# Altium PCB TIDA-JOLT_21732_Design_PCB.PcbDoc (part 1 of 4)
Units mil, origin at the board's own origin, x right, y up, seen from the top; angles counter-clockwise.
Board outline 5511.81 x 3149.61 mil, 4 copper layers (Top Layer, Power, Ground, Bottom Layer), stack 104.204 mil thick; 440 components, 201 nets, 1044 pads, 391 vias.
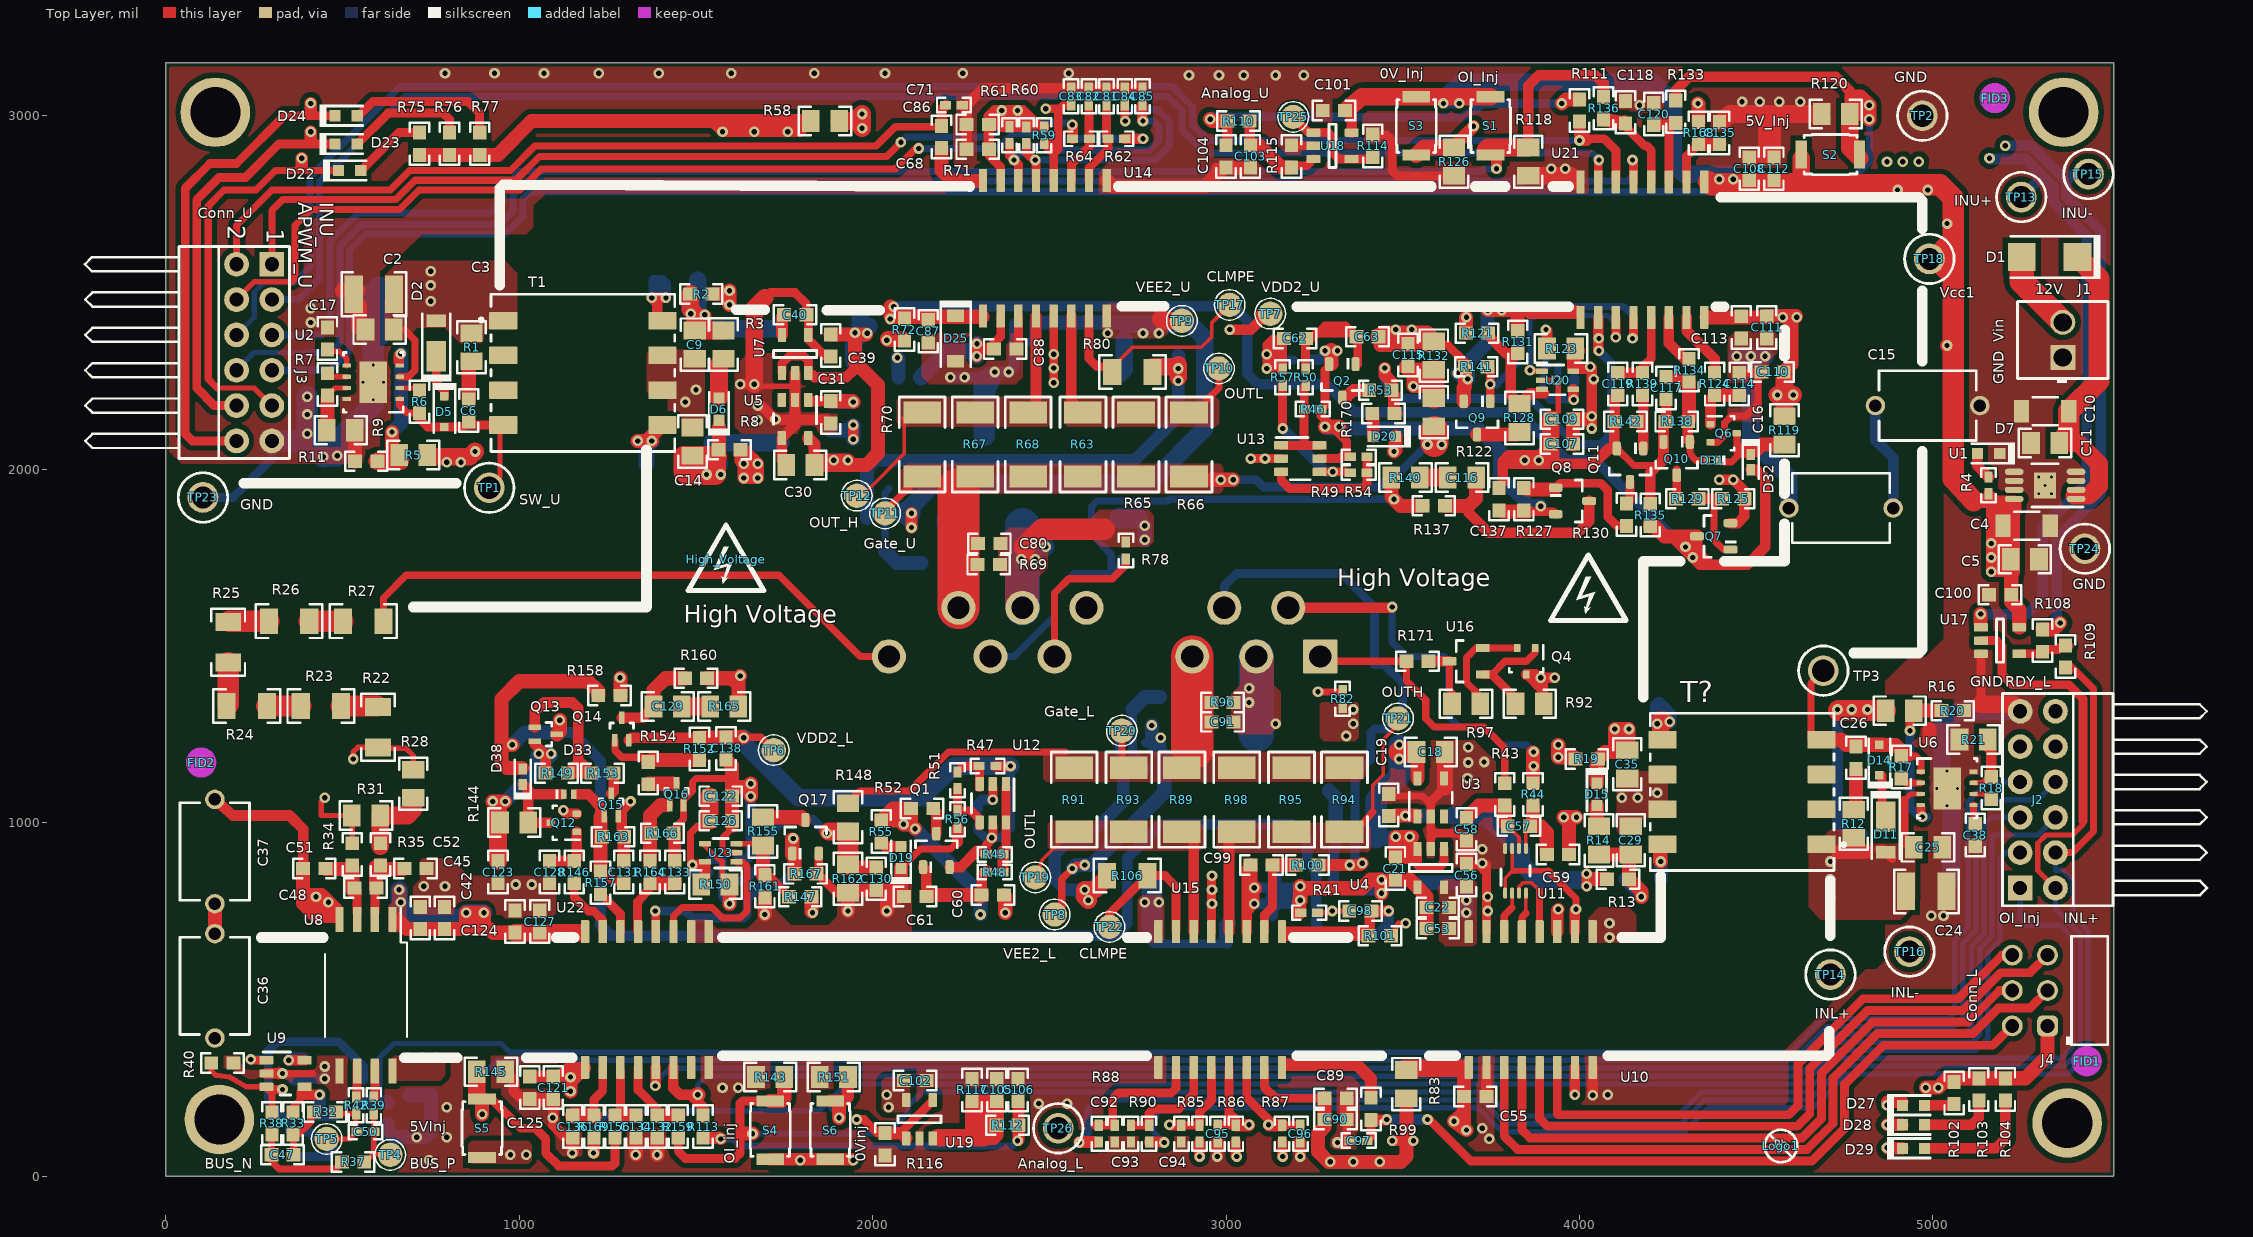
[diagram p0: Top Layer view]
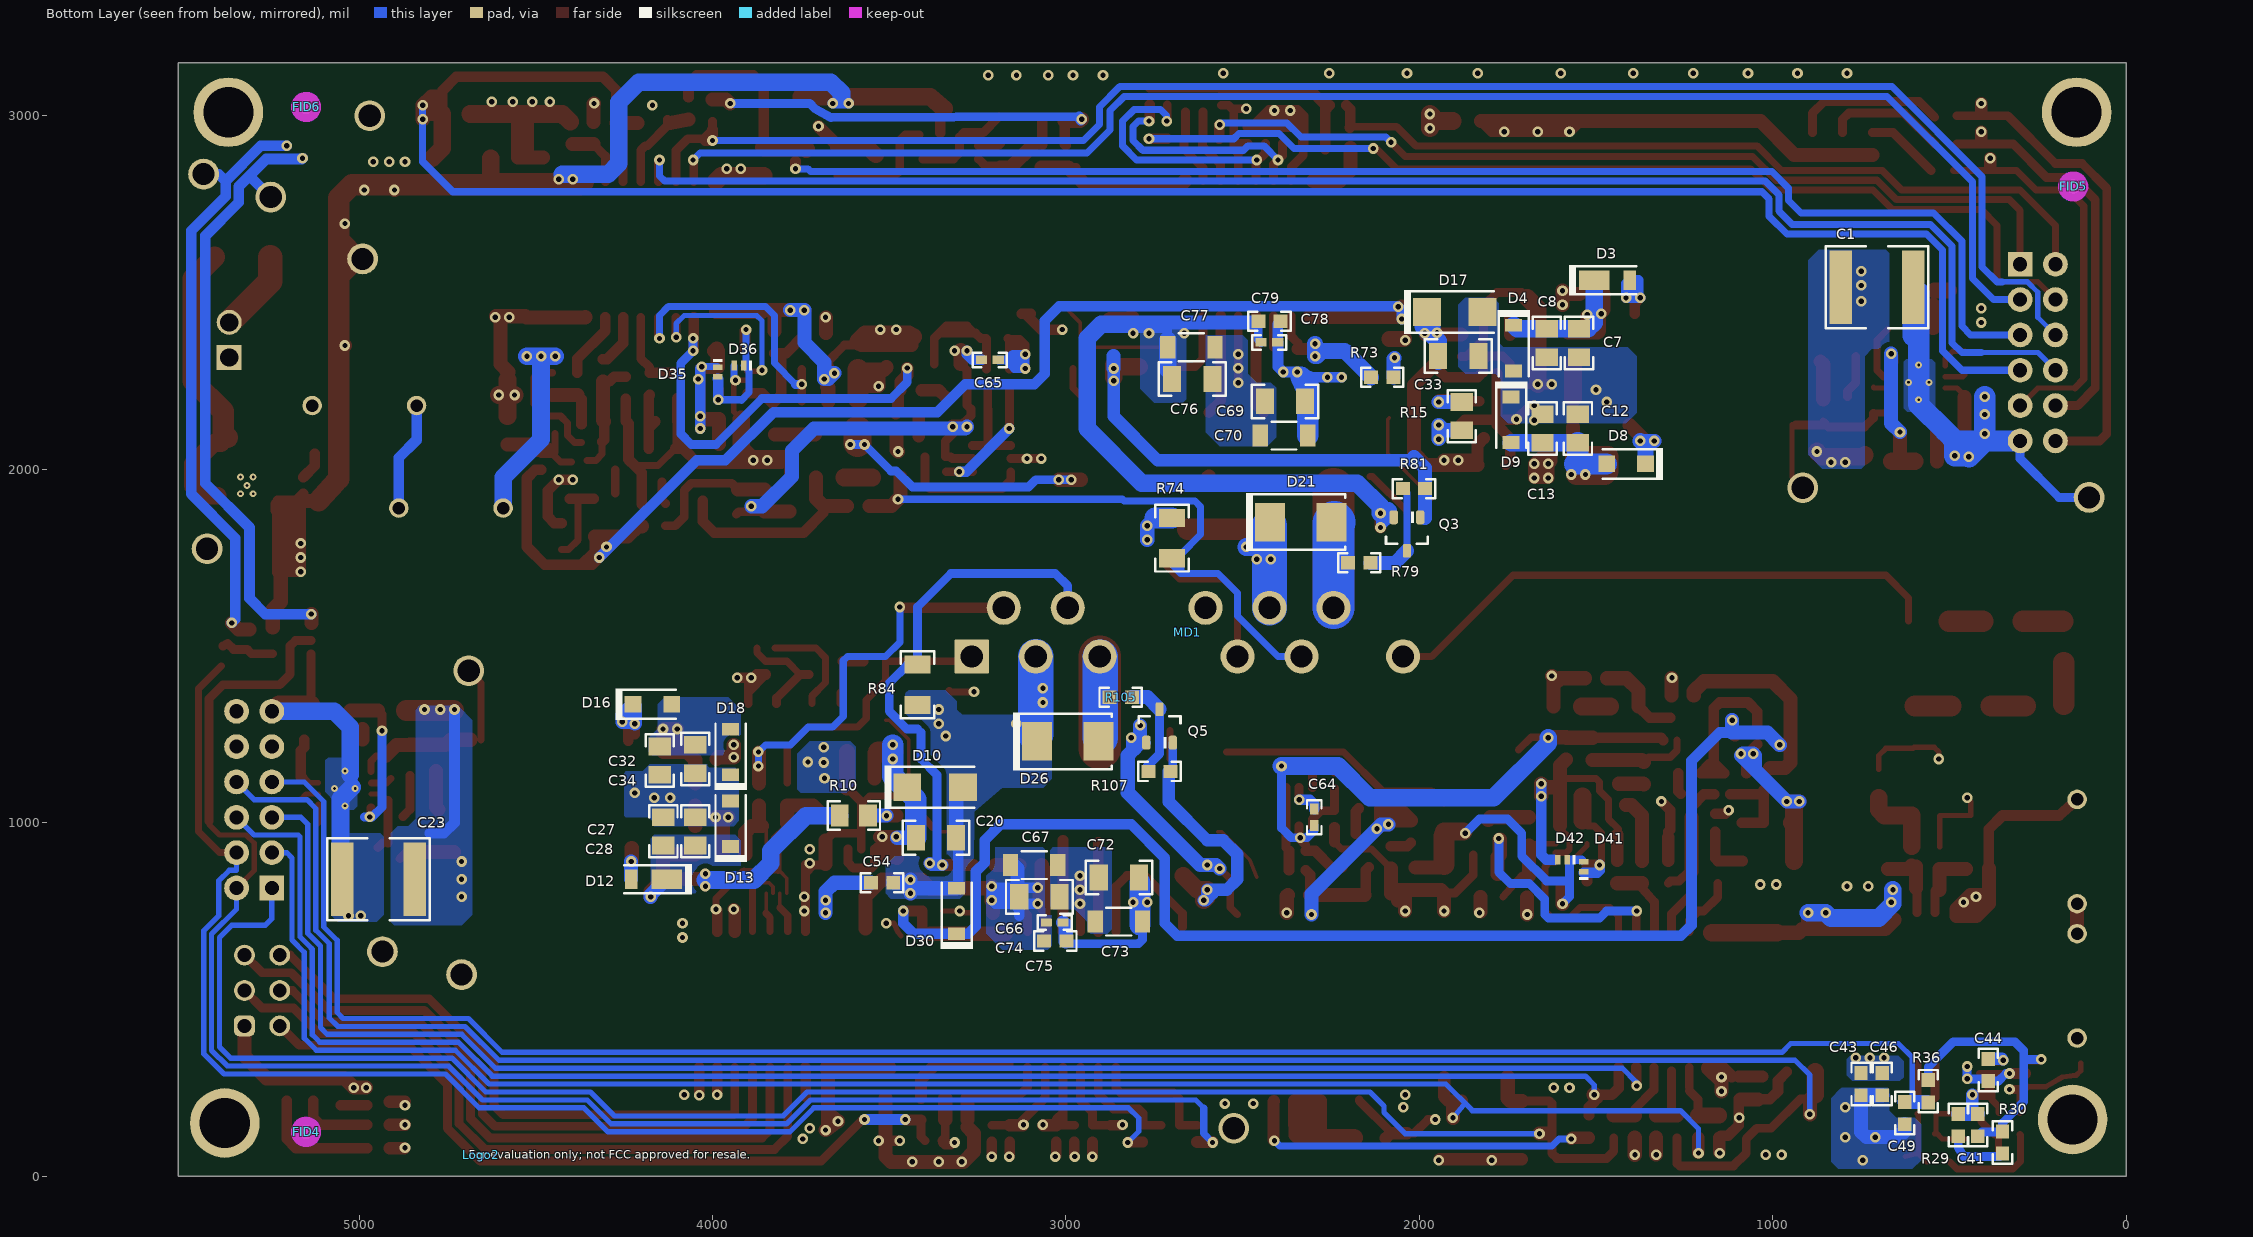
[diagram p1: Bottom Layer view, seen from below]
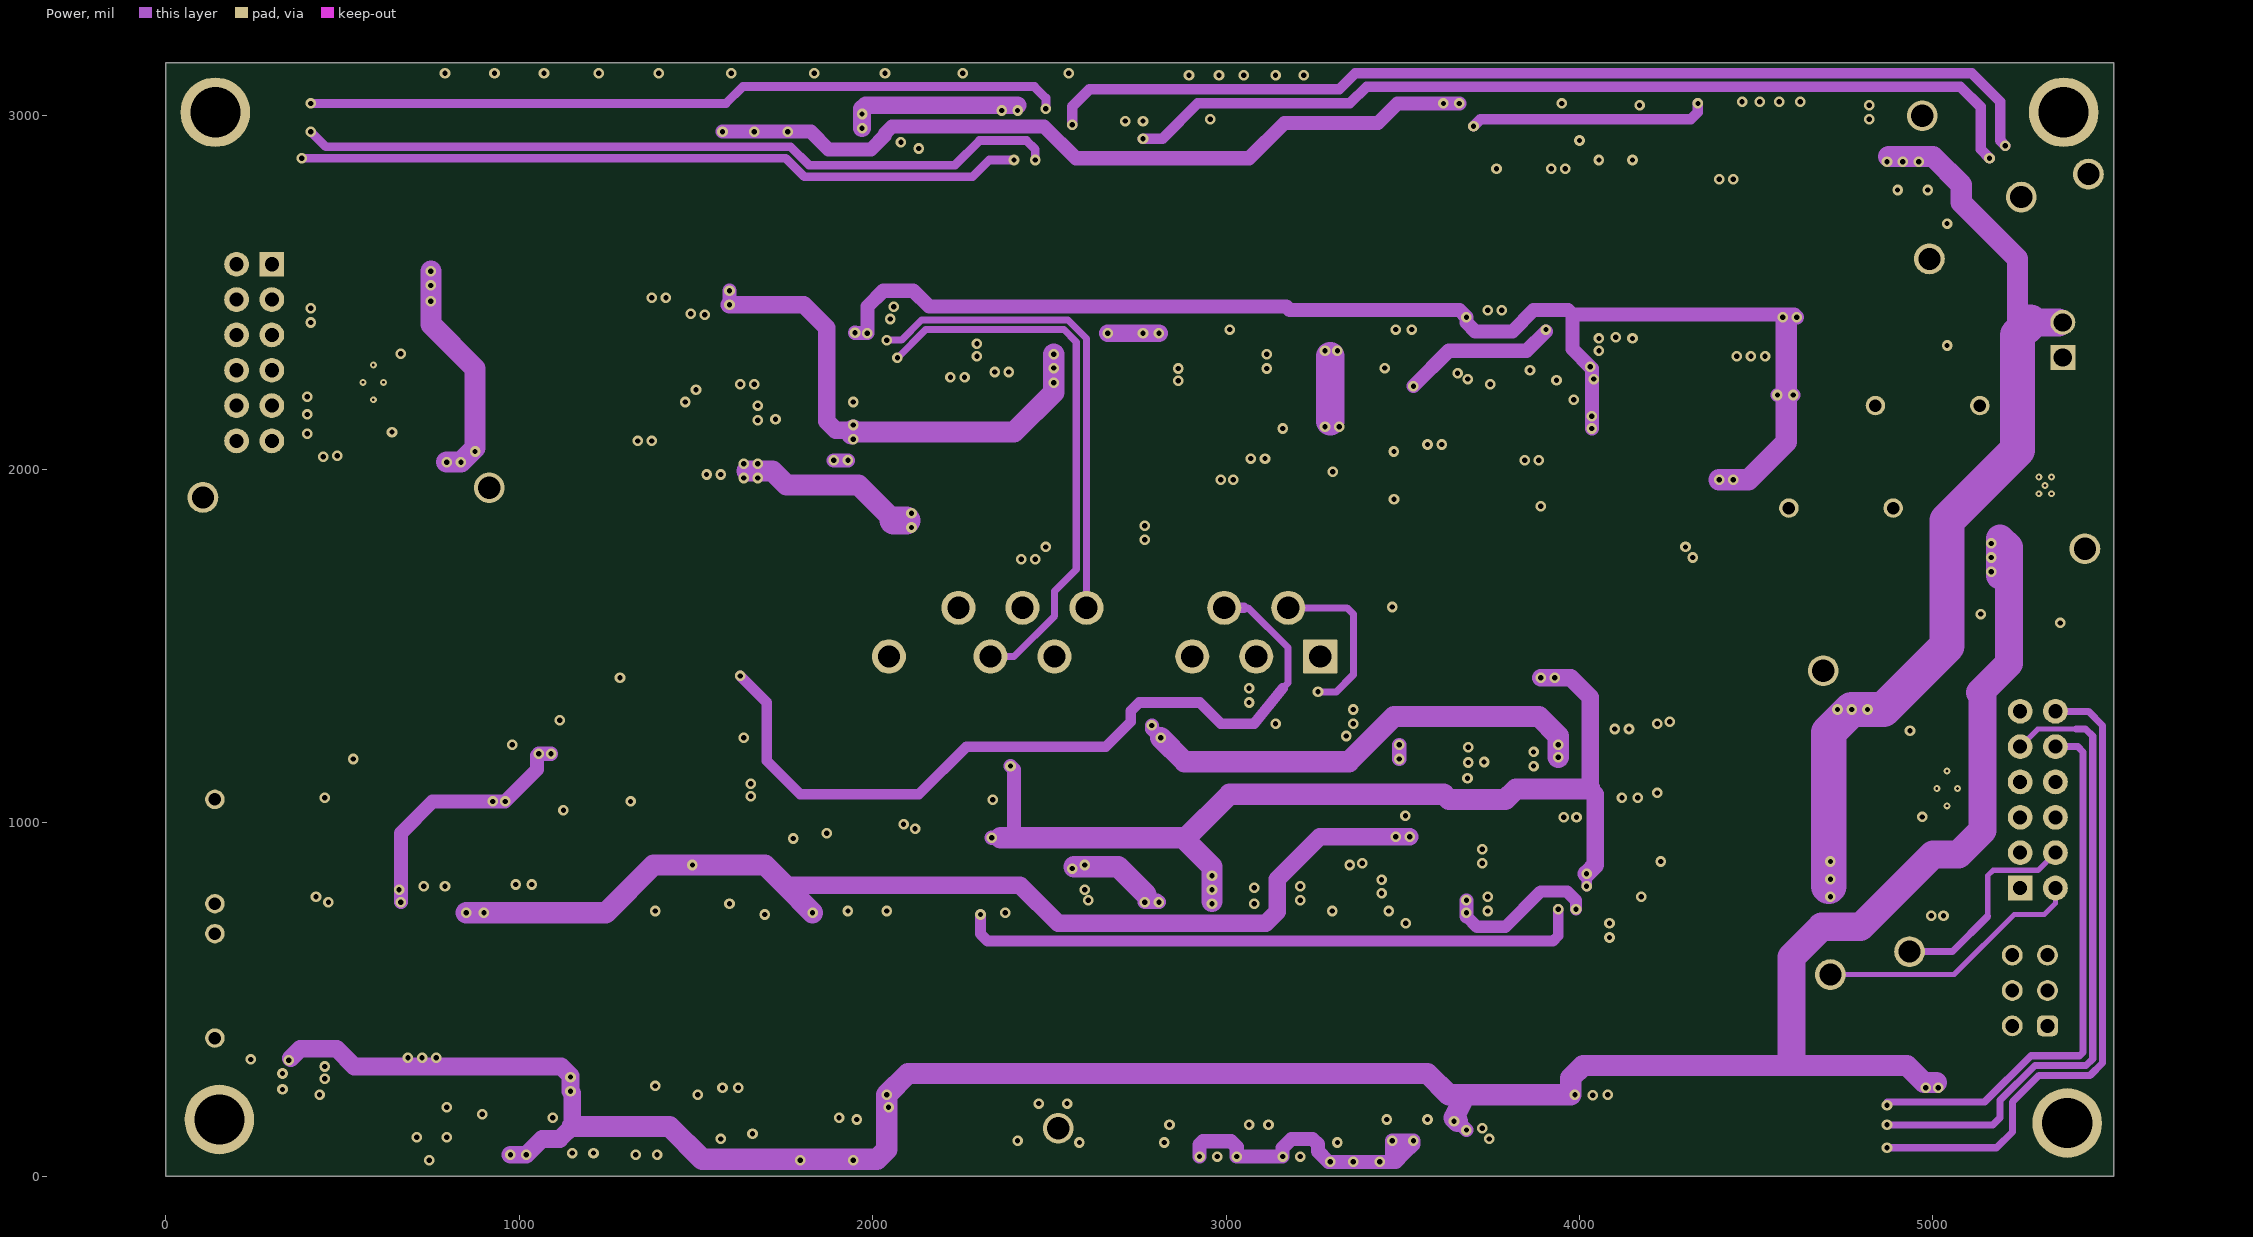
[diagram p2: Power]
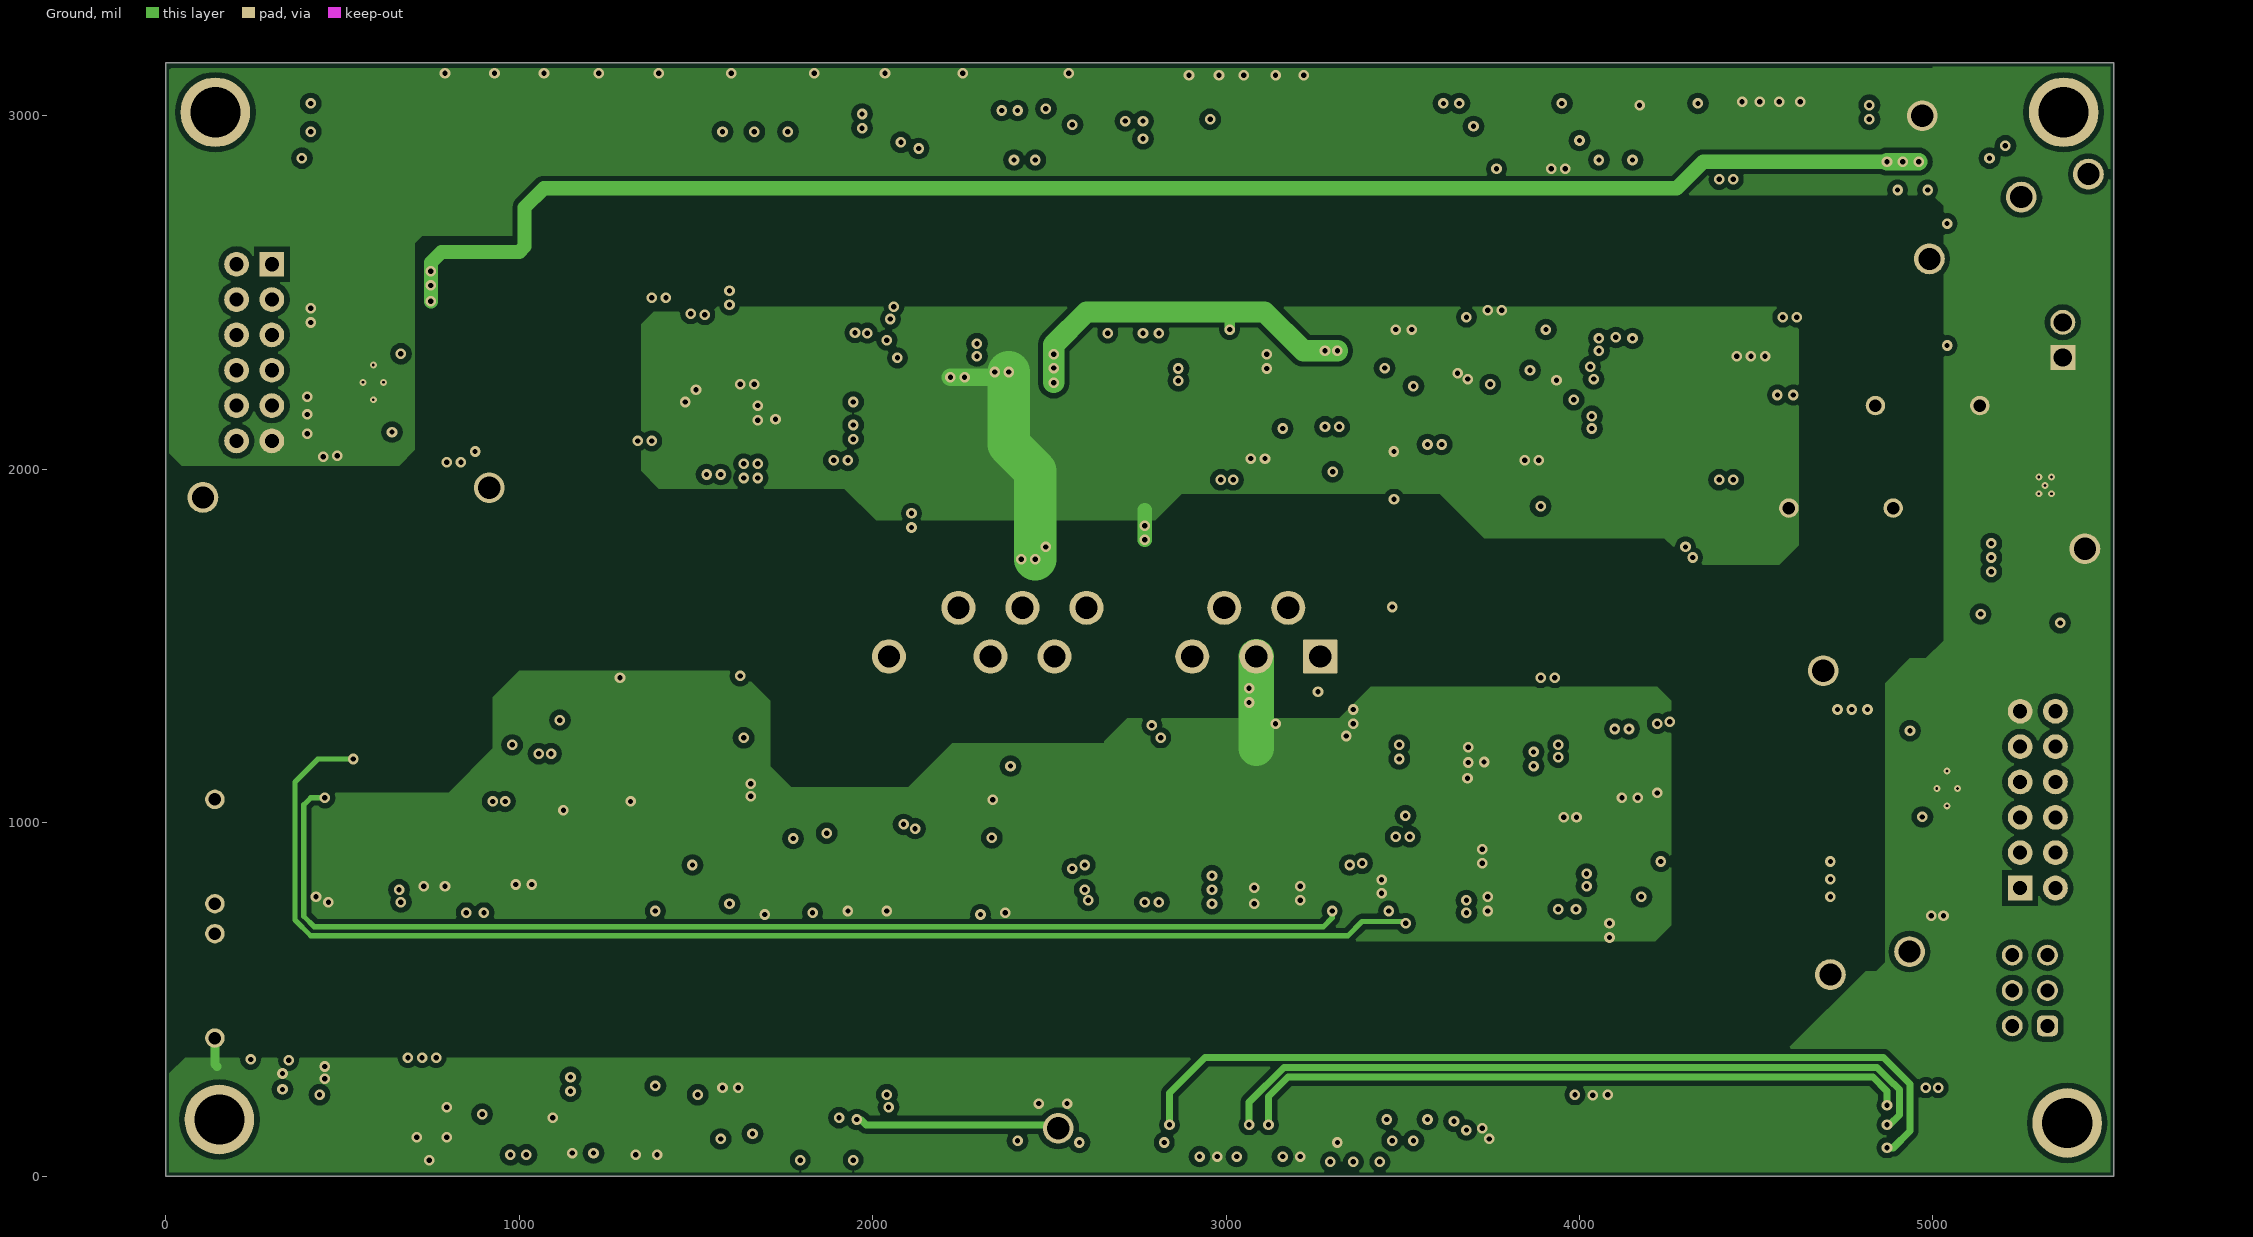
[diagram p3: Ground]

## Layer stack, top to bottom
Top Solder: solder mask 0.4, Solder Resist, Dk 3.5
Top Layer: signal copper 1.4
Dielectric 2: prepreg 19.685, FR-4, Dk 4.2
Power: signal copper 1.417
Dielectric1: core 59.2, FR-4, Dk 4.8
Ground: signal copper 1.417
Dielectric 3: prepreg 19.685, FR-4, Dk 4.2
Bottom Layer: signal copper 1.4
Bottom Solder: solder mask 0.4, Solder Resist, Dk 3.5

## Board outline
0,0 0,3149.61 5511.81,3149.61 5511.81,0

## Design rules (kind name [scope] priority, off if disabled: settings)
AcuteAngle [All] p1: minimum=4.50000000000000E+0001 checktracksonly=FALSE
AssemblyTestPointUsage [All] p1: valid=2
BoardOutlineClearance BoardOutlineClearance_MountingHoles [OnCopper and InComponentClass('Mounting Holes')] p1: gap=40 ignorepadtopadclearanceinfootprint=FALSE
BoardOutlineClearance BoardOutlineClearance_Poly [OnCopper and IsPoly] p2: gap=10 ignorepadtopadclearanceinfootprint=FALSE
BoardOutlineClearance [OnCopper and Not InComponentClass('Logo') and not InComponentClass('FiducialMark') and not InRegion(1000,500,4000,800) and not InPoly] p3: gap=10 ignorepadtopadclearanceinfootprint=FALSE
Clearance Clearance_Keepouts [((IsTrack Or IsArc) And Not InPoly) And IsFree and IsKeepOut vs ((IsTrack Or IsArc) And Not InPoly) And IsFree and IsKeepOut] p1: gap=0 ignorepadtopadclearanceinfootprint=FALSE
Clearance Clearance_Poly [InPolygon] p2: gap=15 ignorepadtopadclearanceinfootprint=FALSE
Clearance Clearance_FiducialMark [IsKeepOut and InComponentClass('FiducialMark') vs IsPad and InComponentClass('FiducialMark')] p3: gap=0 ignorepadtopadclearanceinfootprint=FALSE
Clearance [All] p4: gap=7.45 ignorepadtopadclearanceinfootprint=FALSE
ComponentClearance ComponentClearance_MountingHoles_FiducialMarks [InComponentClass('Mounting Holes') vs InComponentClass('FiducialMark')] p1: gap=50 collisioncheckmode=3 verticalgap=10 showdistances=FALSE
ComponentClearance ComponentClearance_Shunt [InComponentClass('Header') vs InComponentClass('Shunt')] p2: gap=0 collisioncheckmode=3 verticalgap=0 showdistances=FALSE
ComponentClearance ComponentClearance_Logo [InComponentClass('Logo')] p3: gap=50 collisioncheckmode=3 verticalgap=10 showdistances=FALSE
ComponentClearance ComponentClearance_ScrewToNut [(HasFootprint('NY PMS 440 0025 PH')) vs (HasFootprint('Keystone_1902C'))] p4: gap=5 collisioncheckmode=3 verticalgap=10 showdistances=FALSE
ComponentClearance ComponentClearance_MountingHoles [InComponentClass('Mounting Holes')] p5: gap=250 collisioncheckmode=3 verticalgap=100000 showdistances=FALSE
ComponentClearance ComponentClearance_SmallPassives [HasFootprint('0201*') or HasFootprint('0402*') or HasFootprint('0508') or HasFootprint('0603*') or HasFootprint('0612') or HasFootprint('0805*') or HasFootprint('0815*') or HasFootprint('0830*') or HasFootprint('1206*') or HasFootprint('1210*') or HasFootprint('1808*') or HasFootprint('1812*') or HasFootprint('1825*') or HasFootprint('2010*') or HasFootprint('2220*') or HasFootprint('2225*') or HasFootprint('2512*') or HasFootprint('2728*') or HasFootprint('3518*') vs HasFootprint('0201*') or HasFootprint('0402*') or HasFootprint('0508') or HasFootprint('0603*') or HasFootprint('0612') or HasFootprint('0805*') or HasFootprint('0815*') or HasFootprint('0830*') or HasFootprint('1206*') or HasFootprint('1210*') or HasFootprint('1808*') or HasFootprint('1812*') or HasFootprint('1825*') or HasFootprint('2010*') or HasFootprint('2220*') or HasFootprint('2225*') or HasFootprint('2512*') or HasFootprint('2728*') or HasFootprint('3518*')] p6: gap=14.96 collisioncheckmode=3 verticalgap=10 showdistances=FALSE
ComponentClearance ComponentClearance_THtoSMT [IsThruComponent vs IsSMTComponent] p7: gap=30 collisioncheckmode=3 verticalgap=30 showdistances=FALSE
ComponentClearance ComponentClearance_THtoTH [IsThruComponent vs IsThruComponent] p8: gap=30 collisioncheckmode=3 verticalgap=30 showdistances=FALSE
ComponentClearance [All] p9: gap=15 collisioncheckmode=3 verticalgap=10 showdistances=FALSE
DiffPairsRouting [All] p1: maxlimit=100 minlimit=10 mostfreqgap=10 toplayer_minwidth=15 toplayer_maxwidth=15 toplayer_prefwidth=15 midlayer1_minwidth=15 midlayer1_maxwidth=15 midlayer1_prefwidth=15 midlayer2_minwidth=15 midlayer2_maxwidth=15 midlayer2_prefwidth=15 bottomlayer_minwidth=15 bottomlayer_maxwidth=15 bottomlayer_prefwidth=15 maxuncoupledlength=1000
FabricationTestPointUsage TestPointUsage [All] p1: valid=2 allowmultiple=FALSE
FabricationTestpoint Testpoint [All] p1: side=3 testpointundercomponent=TRUE minsize=40 maxsize=100 preferedsize=60 minholesize=0 maxholesize=40 preferedholesize=32 testpointgrid=1 allowsidetop=TRUE allowsidebottom=TRUE usegrid=TRUE gridtolerance=0.01
FanoutControl Fanout_LCC [IsLCC] p1: bgadir=Out bgaviamode=Centered fanoutstyle=Auto fanoutdirection=Alternating viagrid=1 // Fanout_LCC (Default Rule)
FanoutControl Fanout_BGA [IsBGA] p2: bgadir=Out bgaviamode=Centered fanoutstyle=Auto fanoutdirection=Alternating viagrid=1 // Fanout_BGA (Default Rule)
FanoutControl Fanout_Default [All] p4: bgadir=Out bgaviamode=Centered fanoutstyle=Auto fanoutdirection=Alternating viagrid=1 // Fanout_Default (Default Rule)
FanoutControl Fanout_Small [(CompPinCount < 5)] p5: bgadir=Out bgaviamode=Centered fanoutstyle=Auto fanoutdirection=OutThenIn viagrid=1 // Fanout_Small (Default Rule)
Height [All] p1: minheight=0 maxheight=2500 prefheight=500
HoleSize [All] p1: absolutevalues=TRUE maxlimit=251 minlimit=7.87 maxpercent=80.000 minpercent=20.000
MinimumAnnularRing MinimumAnnularRing_ThermalPadVias [IsVia and InAnyComponent] p1: minimumring=5.91
MinimumAnnularRing [All] p2: minimumring=7
MinimumSolderMaskSliver MinimumSolderMaskSliver_Logo [InComponentClass('Logo') vs InComponentClass('Logo')] p1: minsoldermaskwidth=0.7
MinimumSolderMaskSliver [All] p2: minsoldermaskwidth=0
PlaneConnect [All] p1: planeconnectstyle=Direct reliefexpansion=10 reliefentries=4 reliefconductorwidth=10 reliefairgap=10
PolygonConnect [All] p1: connectstyle=Direct reliefconductorwidth=10 reliefentries=4 polygonreliefangle="90 Angle" airgapwidth=10
RoutingVias ThermalPadVias [IsVia and InAnyComponent] p1: holewidth=7.87 width=19.68 viastyle="Through Hole" minholewidth=7.87 minwidth=19.68 maxholewidth=12.99 maxwidth=23.62
RoutingVias [All] p2: holewidth=16 width=34 viastyle="Through Hole" minholewidth=7.87 minwidth=26 maxholewidth=40 maxwidth=65
SilkToBoardRegionClearance [Not ((IsComment or IsDesignator) And (Hide <> 'False')) and not InRegion(1000,500,4000,800)] p1:
SilkToSilkClearance SilkToSilkClearance_Pb-FreeLogo [(HasFootprint('Pb-Free_Overlay_Medium') OR HasFootprint('Pb-Free_Overlay_Small')) vs (HasFootprint('Pb-Free_Overlay_Medium') OR HasFootprint('Pb-Free_Overlay_Small'))] p1: silktosilkclearance=0
SilkToSilkClearance [All] p2: silktosilkclearance=4
SilkToSolderMaskClearance SilkToComponentPadClearance [(IsPad or IsFill or IsRegion) and InAnycomponent] p1: minsilkscreentomaskgap=0 clearancetoexposedcopper=TRUE
SilkToSolderMaskClearance "Silk to Solder Mask Opening" [All] p2: minsilkscreentomaskgap=0 clearancetoexposedcopper=FALSE
SolderMaskExpansion [All] p1: expansion=1.97
Width "Schematic Width Constraint" [InNetClass('PowerNets')] p1: maxlimit=120 minlimit=20 preferedwidth=80 midlayer1_minwidth=40 midlayer2_minwidth=40 minimp=50.000000 maximp=50.000000 favimp=50.000000
Width [All] p2: maxlimit=200 minlimit=6 preferedwidth=10 checkconnectedcopper=TRUE
14 further rules are at their usual default settings.

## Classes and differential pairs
component class AssemblyNote: ZZ1 ZZ2 ZZ3 ZZ4
component class FiducialMark: FID1 FID2 FID3 FID4 FID5 FID6
component class JOLT_21732_Design_EVM_Hardware: FID1 FID2 FID3 FID4 FID5 FID6 "High Voltage" High_Voltage Logo1 Logo2 ZZ1 ZZ2 ZZ3 ZZ4
component class Header: J2 J3 J4
component class JOLT_21732_Driver_Conn: C66 C67 C68 C69 C70 C71 C72 C73 C74 C75 C76 C77 C78 C79 C80 C81 C82 C83 C84 C85 C86 C87 C88 C89 C90 C91 C92 C93 C94 C95 C96 C97 C98 C99 C100 D21 D22 D23 D24 D25 D26 D27 D28 D29 D30 J2 J3 J4 MD1 Q3 Q4 Q5 R58 R59 R60 R61 R62 R63 R64 R65 R66 R67 R68 R69 R70 R71 R72 R73 R74 R75 R76 R77 R78 R79 R80 R81 R82 R83 R84 R85 R86 R87 R88 R89 R90 R91 R92 R93 R94 R95 R96 R97 R98 R99 R100 R101 R102 R103 R104 R105 R106 R107 R108 R109 R171 TP6 TP7 TP8 TP9 TP10 TP11 TP12 TP13 TP14 TP15 TP16 TP17 TP18 TP19 TP20 TP21 TP22 TP23 TP24 U14 U15 U16 U17
component class JOLT_21732_OI_AIN_PWM_check: C101 C102 C103 C104 C105 C106 C107 C108 C109 C110 C111 C112 C113 C114 C115 C116 C117 C118 C119 C120 C121 C122 C123 C124 C125 C126 C127 C128 C129 C130 C131 C132 C133 C134 C135 C136 C137 C138 D31 D32 D33 D35 D36 D38 D41 D42 Q6 Q7 Q8 Q9 Q10 Q11 Q12 Q13 Q14 Q15 Q16 Q17 R110 R111 R112 R113 R114 R115 R116 R117 R118 R119 R120 R121 R122 R123 R124 R125 R126 R127 R128 R129 R130 R131 R132 R133 R134 R135 R136 R137 R138 R139 R140 R141 R142 R143 R144 R145 R146 R147 R148 R149 R150 R151 R152 R153 R154 R155 R156 R157 R158 R159 R160 R161 R162 R163 R164 R165 R166 R167 R168 R169 S1 S2 S3 S4 S5 S6 TP25 TP26 U18 U19 U20 U21 U22 U23
component class JOLT_21732_Supply_Bias: C1 C2 C3 C4 C5 C6 C7 C8 C9 C10 C11 C12 C13 C14 C15 C16 C17 C18 C19 C20 C21 C22 C23 C24 C25 C26 C27 C28 C29 C30 C31 C32 C33 C34 C35 C36 C37 C38 C39 C40 D1 D2 D3 D4 D5 D6 D7 D8 D9 D10 D11 D12 D13 D14 D15 D16 D17 D18 J1 R1 R2 R3 R4 R5 R6 R7 R8 R9 R10 R11 R12 R13 R14 R15 R16 R17 R18 R19 R20 R21 T1 T? TP1 TP2 TP3 U1 U2 U3 U4 U5 U6 U7
net class PowerNets: +5V_L +5V_U VCC1
differential pair BUSIN: +BUSIN_P -BUSIN_N
differential pair BUS: +BUS_P -BUS_N

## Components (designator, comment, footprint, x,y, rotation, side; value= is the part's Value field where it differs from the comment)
C1 "C5750X7S2A106K230KB" 2220_250 705,2515 r180 bottom value=10uF
C2 "GCM32DC72A475KE02L" 1210_220 588.86,2495 r180 top value=4.7uF
C3 "GRM21BR72A104KAC4L" 0805_HV 605,2395 r180 top value=0.1uF
C4 "GRM31CR71E106KA12L" 1206_180 5265,1840 r0 top value=10uF
C5 "GRM21BR71H104KA01L" 0805_HV 5260,1745 r0 top value=0.1uF
C6 "GRM1885C2A221JA01D" 0603 857.1,2165.76 r270 top value=220pF
C7 "GRM21BR61E226ME44L" 0805_HV 1548.2,2357.02 r270 bottom value=22uF
C8 "GRM21BR61E226ME44L" 0805_HV 1639.22,2357.02 r270 bottom value=22uF
C9 "GRM21BR71H224KA01L" 0805_HV 1496.85,2352.39 r270 top value=0.22uF
C10 "GRM31CR71H225KA88L" 1206_180 5317.4,2164.13 r180 top value=2.2uF
C11 "GRM21BR71H104KA01L" 0805_HV 5317.4,2074.13 r180 top value=0.1uF
C12 "GRM21BR61E226ME44L" 0805_HV 1551.46,2115 r270 bottom value=22uF
C13 "GRM21BR61E226ME44L" 0805_HV 1651.46,2115 r270 bottom value=22uF
C14 "GRM21BR71H224KA01L" 0805_HV 1490,2078.03 r270 top value=0.22uF
C15 "DE2E3KY152MN3AM02F" KY_700x500x1000 4985,2180 r0 top value=1500pF
C16 "DE2E3KY152MN3AM02F" KY_700x500x1000 4740,1890 r0 top value=1500pF
C17 "GRM188R71C473KA01D" 0603 457.1,2370 r90 top value=0.047uF
C18 "C2012X5R1E106K125AB" 0805_HV 3578.98,1200 r180 top value=10uF
C19 "UMK107AB7105KA-T" 0603 3460,1050 r90 top value=1uF
C20 "C1206C225K4RACTU" 1206 3367.56,957.27 r180 bottom value=2.2uF
C21 "GRM188R71E105KA12D" 0603 3478.98,870 r270 top value=1uF
C22 "GRM188R71E105KA12D" 0603 3598.98,760 r180 top value=1uF
C23 "C5750X7S2A106K230KB" 2220_250 4945,840 r0 bottom value=10uF
C24 "GCM32DC72A475KE02L" 1210_220 4981.3,805.47 r0 top value=4.7uF
C25 "GRM21BR72A104KAC4L" 0805_HV 4986.1,930 r0 top value=0.1uF
C26 "GRM1885C2A221JA01D" 0603 4782.41,1183.46 r90 top value=220pF
C27 "GRM21BR61E226ME44L" 0805_HV 4138.98,975.35 r90 bottom value=22uF
C28 "GRM21BR61E226ME44L" 0805_HV 4048.98,975.35 r90 bottom value=22uF
C29 "GRM21BR71H224KA01L" 0805_HV 4145,950 r90 top value=0.22uF
C30 "C2012X5R1E106K125AB" 0805_HV 1795.28,2012.14 r0 top value=10uF
C31 "UMK107AB7105KA-T" 0603 1881.3,2160.88 r270 top value=1uF
C32 "GRM21BR61E226ME44L" 0805_HV 4148.98,1175.35 r90 bottom value=22uF
C33 "C1206C225K4RACTU" 1206 1889.75,2320.57 r180 bottom value=2.2uF
C34 "GRM21BR61E226ME44L" 0805_HV 4048.98,1180 r90 bottom value=22uF
C35 "GRM21BR71H224KA01L" 0805_HV 4135,1165 r90 top value=0.22uF
C36 "DE2E3KY152MN3AM02F" KY_700x500x1000 138.7,538.11 r270 top value=1500pF
C37 "DE2E3KY152MN3AM02F" KY_700x500x1000 138.7,918.11 r270 top value=1500pF
C38 "GRM188R71C473KA01D" 0603 5120,964.87 r270 top value=0.047uF
C39 "GRM188R71E105KA12D" 0603 1881.3,2350 r270 top value=1uF
C40 "GRM188R71E105KA12D" 0603 1780.7,2437.14 r0 top value=1uF
C41 "GRM188R71H103KA01D" 0603 420,144.13 r270 bottom value=0.01uF
C42 "GRM188R71H104KA93D" 0603 788.74,730 r90 top value=0.1uF
C43 "GRM188R71H104KA93D" 0603 750,260 r270 bottom value=0.1uF
C44 "GRM188R71E105KA12D" 0603 390,300 r90 bottom value=1uF
C45 "GRM188R71E105KA12D" 0603 720.04,730 r270 top value=1uF
C46 "GRM188R71E105KA12D" 0603 690,260 r90 bottom value=1uF
C47 "GRM188R71H103KA01D" 0603 330,60 r180 top value=0.01uF
C48 "GRM188R71H103KA01D" 0603 565,815 r0 top value=0.01uF
C49 "GRM188R71H104KA93D" 0603 626.69,178.03 r270 bottom value=0.1uF
C50 "Capacitor" 0402 565,125 r180 top value=0.1uF
C51 "GRM188R71H102KA01D" 0603 420,870 r180 top value=1000pF
C52 "GRM188R71H102KA01D" 0603 706.38,870 r0 top value=1000pF
C53 "GRM188R71E105KA12D" 0603 3598.98,700 r0 top value=1uF
C54 "GRM188R71E105KA12D" 0603 3520,830 r180 bottom value=1uF
C55 "GRM188R71E105KA12D" 0603 3705,225 r180 top value=1uF
C56 "GRM188R71H104KA93D" 0603 3680.28,851.26 r270 top value=0.1uF
C57 "GRM188R71H103KA01D" 0603 3828.5,990 r180 top value=0.01uF
C58 "GRM188R71H102KA01D" 0603 3680.28,981.26 r90 top value=1000pF
C59 "GRM188R71H102KA01D" 0603 3938.98,910 r180 top value=1000pF
C60 "GRM1885C2A101JA01D" 0603 2340,795 r0 top value=100pF
C61 "GRM1885C2A101JA01D" 0603 2120.24,791.26 r180 top value=100pF
C62 "GRM1885C2A101JA01D" 0603 3195,2370 r180 top value=100pF
C63 "GRM1885C2A101JA01D" 0603 3400,2375 r0 top value=100pF
C64 "Capacitor" 0402 2297.32,1015 r90 bottom value=0.1uF
C65 "Capacitor" 0402 3215,2309.21 r180 bottom value=0.1uF
C66 "C1206C104J5RACTU" 1206 3075,790 r0 bottom value=0.1uF
C67 "C3216X7R1H105K160AB" 1206_180 3090,880 r0 bottom value=1uF
C68 "GRM188R71E105KA12D" 0603 2297.18,2905.35 r0 top value=1uF
C69 "C1206C104J5RACTU" 1206 2380,2191.89 r180 bottom value=0.1uF
C70 "C3216X7R1H105K160AB" 1206_180 2382.91,2095 r180 bottom value=1uF
C71 "GRM188R71H104KA93D" 0603 2297.18,2975.35 r180 top value=0.1uF
C72 "C1206C104J5RACTU" 1206 2850,845 r180 bottom value=0.1uF
C73 "C3216X7R1H105K160AB" 1206_180 2850,720 r180 bottom value=1uF
C74 "GCM155R71C104KA55D" 0402 3031.8,717.32 r180 bottom value=0.1uF
C75 "UMK107AB7105KA-T" 0603 3030,665 r180 bottom value=1uF
C76 "C1206C104J5RACTU" 1206 2642.48,2255 r0 bottom value=0.1uF
C77 "C3216X7R1H105K160AB" 1206_180 2645,2345 r0 bottom value=1uF
C78 "GCM155R71C104KA55D" 0402 2424.09,2358.7 r0 bottom value=0.1uF
C79 "UMK107AB7105KA-T" 0603 2424.09,2418.7 r0 bottom value=1uF
C80 "GRM188R71H103KA01D" 0603 2330,1790 r0 top value=0.01uF
C81 "CC0402JRNPO9BN101" 0402 2661.65,3054.72 r90 top value=100pF
C82 "CC0402JRNPO9BN101" 0402 2611.65,3054.72 r90 top value=100pF
C83 "CC0402JRNPO9BN101" 0402 2561.65,3054.72 r90 top value=100pF
C84 "CC0402JRNPO9BN101" 0402 2713.31,3054.72 r90 top value=100pF
C85 "CC0402JRNPO9BN101" 0402 2763.31,3054.72 r90 top value=100pF
C86 "GRM155R71C222KA01D" 0402 2230,3030 r0 top value=2200pF
C87 "SR0603X7R103K1NT95(F)#M123A" 0603 2157.18,2390.35 r270 top value=0.01uF
C88 "SR0603X7R103K1NT95(F)#M123A" 0603 2375,2340 r0 top value=0.01uF
C89 "GRM188R71E105KA12D" 0603 3310,220 r180 top value=1uF
C90 "GRM188R71H104KA93D" 0603 3310,160 r0 top value=0.1uF
C91 "GRM188R71H103KA01D" 0603 2990,1285 r0 top value=0.01uF
C92 "CC0402JRNPO9BN101" 0402 2685,120 r270 top value=100pF
C93 "CC0402JRNPO9BN101" 0402 2730.81,120 r270 top value=100pF
C94 "CC0402JRNPO9BN101" 0402 2873.44,120 r270 top value=100pF
C95 "CC0402JRNPO9BN101" 0402 2976.06,120 r270 top value=100pF
C96 "CC0402JRNPO9BN101" 0402 3210,120 r270 top value=100pF
C97 "GRM155R71C222KA01D" 0402 3375,100 r180 top value=2200pF
C98 "SR0603X7R103K1NT95(F)#M123A" 0603 3380,750 r180 top value=0.01uF
C99 "SR0603X7R103K1NT95(F)#M123A" 0603 3100,880 r180 top value=0.01uF
C100 "GRM188R71H104KA93D" 0603 5190,1645 r180 top value=0.1uF
C101 "GRM188R71E105KA12D" 0603 3305,3015 r0 top value=1uF
C102 "GRM188R71E105KA12D" 0603 2120.29,270 r180 top value=1uF
C103 "GRM188R71E105KA12D" 0603 3068.7,2885 r270 top value=1uF
C104 "GRM188R71H104KA93D" 0603 3000,2885 r90 top value=0.1uF
C105 "GRM188R71E105KA12D" 0603 2351.3,243.5 r90 top value=1uF
C106 "GRM188R71H104KA93D" 0603 2411.3,243.5 r270 top value=0.1uF
C107 "GRM188R71H104KA93D" 0603 3950,2071.3 r0 top value=0.1uF
C108 "GRM188R71E105KA12D" 0603 4480,2850 r270 top value=1uF
C109 "GRM1885C1H101JA01D" 0603 3950,2141.3 r180 top value=100pF
C110 "GRM188R71E105KA12D" 0603 4546.3,2275.29 r180 top value=1uF
C111 "GRM188R71E105KA12D" 0603 4529.8,2401.3 r90 top value=1uF
C112 "GRM188R71H104KA93D" 0603 4550,2850 r90 top value=0.1uF
C113 "GRM188R71H104KA93D" 0603 4457.91,2401.3 r90 top value=0.1uF
C114 "GRM1885C1H101JA01D" 0603 4452.24,2241.3 r90 top value=100pF
C115 "GRM1885C1H470JA01D" 0603 3515,2323.5 r90 top value=47pF
C116 "GRM219R71H334KA88D" 0805_HV 3667.52,1976.3 r180 top value=0.33uF
C117 "GRM188R71E222KA01D" 0603 4245,2230 r270 top value=2200pF
C118 "GRM1885C1H471JA01D" 0603 4130,3010 r270 top value=470pF
C119 "GRM1885C1H101JA01D" 0603 4107.91,2241.3 r270 top value=100pF
C120 "GRM1885C1H471JA01D" 0603 4210,3005 r270 top value=470pF
C121 "GRM188R71E105KA12D" 0603 1096.3,250 r90 top value=1uF
C122 "GRM188R71H104KA93D" 0603 1570,1075 r180 top value=0.1uF
C123 "GRM188R71E105KA12D" 0603 940,860 r270 top value=1uF
C124 "GRM188R71E105KA12D" 0603 988.11,720 r270 top value=1uF
C125 "GRM188R71H104KA93D" 0603 1030,250 r270 top value=0.1uF
C126 "GRM1885C1H101JA01D" 0603 1570,1005 r0 top value=100pF
C127 "GRM188R71H104KA93D" 0603 1058.11,720 r270 top value=0.1uF
C128 "GRM1885C1H101JA01D" 0603 1085.67,860 r270 top value=100pF
C129 "GRM219R71H334KA88D" 0805_HV 1420,1328.54 r0 top value=0.33uF
C130 "GRM1885C1H470JA01D" 0603 2010,841.26 r270 top value=47pF
C131 "GRM188R71E222KA01D" 0603 1295.67,860 r90 top value=2200pF
C132 "GRM1885C1H471JA01D" 0603 1390.29,140 r90 top value=470pF
C133 "GRM1885C1H101JA01D" 0603 1440,860 r90 top value=100pF
C134 "GRM1885C1H471JA01D" 0603 1330.58,140 r90 top value=470pF
C135 "GRM1885C1H471JA01D" 0603 4396.46,2951.3 r270 top value=470pF
C136 "GRM1885C1H471JA01D" 0603 1151.46,140 r90 top value=470pF
C137 "GRM188R71E105KA12D" 0603 3772.52,1915 r90 top value=1uF
C138 "GRM188R71E105KA12D" 0603 1585,1210 r270 top value=1uF
D1 "B260A-13-F" SMA 5330,2600 r180 top value=60V
D2 "DFLZ24-7" PowerDI123 765,2370 r90 top value=24V
D3 "DFLU1200-7" PowerDI123 1455,2535 r180 bottom value=200V
D4 "BZT52C18-7-F" SOD-123 1733.2,2342.61 r270 bottom value=18V
D5 "CMDD4448" SOD-323 788.2,2162.61 r270 top value=75V
D6 "150060GS75000" WL-SMCW_GREEN 1565,2170 r90 top value=Green
D7 "150060GS75000" WL-SMCW_GREEN 5157.4,2044.13 r180 top value=Green
D8 "PMEG10010ELRX" SOD-123W 1415,2015 r0 bottom value=100V
D9 "BZT52C8V2-7-F" SOD-123 1740,2140 r270 bottom value=8.2V
D10 "SMAZ5V1-13-F" SMA 3370,1100 r180 bottom value=5.1V
D11 "DFLZ24-7" PowerDI123 4866.1,966.85 r270 top value=24V
D12 "DFLU1200-7" PowerDI123 4180,840 r0 bottom value=200V
D13 "BZT52C18-7-F" SOD-123 3948.98,996.85 r90 bottom value=18V
D14 "CMDD4448" SOD-323 4848.6,1177.05 r90 top value=75V
D15 "150060GS75000" WL-SMCW_GREEN 4048.98,1080 r270 top value=Green
D16 "PMEG10010ELRX" SOD-123W 4170,1335 r180 bottom value=100V
D17 "SMAZ5V1-13-F" SMA 1900,2445 r180 bottom value=5.1V
D18 "BZT52C8V2-7-F" SOD-123 3948.98,1200 r90 bottom value=8.2V
D19 "150060SS75000" WL-SMCW_RED 2080.24,901.26 r90 top value="Super Red"
D20 "150060SS75000" WL-SMCW_RED 3447.97,2092.76 r180 top value="Super Red"
D21 "SMBJ20CA" SMB 2335,1850 r180 bottom value=19V
D22 "150060SS75000" WL-SMCW_RED 520,2845 r0 top value="Super Red"
D23 "150060SS75000" WL-SMCW_RED 510,2920 r0 top value="Super Red"
D24 "150060SS75000" WL-SMCW_RED 510,3000 r0 top value="Super Red"
D25 "MMSZ4688-E3-08" SOD-123 2235,2370 r270 top value=4.7V
D26 "SMBJ20CA" SMB 2995,1230 r180 bottom value=19V
D27 "150060SS75000" WL-SMCW_RED 4945,200 r0 top value="Super Red"
D28 "150060SS75000" WL-SMCW_RED 4945,145 r0 top value="Super Red"
D29 "150060SS75000" WL-SMCW_RED 4945,78.35 r0 top value="Super Red"
D30 "MMSZ4688-E3-08" SOD-123 3308.98,750 r90 bottom value=4.7V
D31 "RB521CS30L,315" SOD882 4375,2025 r180 top value=30V
D32 "1N4148X-TP" SOD-523 4485,2020 r270 top value=75V
D33 "RB521CS30L,315" SOD882 1140,1080 r0 top value=30V
D35 "RB521CS30L,315" SOD882 3985,2275 r270 bottom value=30V
D36 "RB521CS30L,315" SOD882 3925,2293.62 r0 bottom value=30V
D38 "1N4148X-TP" SOD-523 1010,1130 r90 top value=75V
D41 "RB521CS30L,315" SOD882 1535,875 r90 bottom value=30V
D42 "RB521CS30L,315" SOD882 1595,895 r0 bottom value=30V
FID1 "Fiducial" Fiducial10-20 5435,325 r0 top
FID2 "Fiducial" Fiducial10-20 100,1170 r0 top
FID3 "Fiducial" Fiducial10-20 5175,3050 r0 top
FID4 "Fiducial" Fiducial10-20 5150,125 r180 bottom
FID5 "Fiducial" Fiducial10-20 150,2800 r0 bottom
FID6 "Fiducial" Fiducial10-20 5150,3025 r180 bottom
"High Voltage" "DANGER HIGH VOLTAGE" IEC_HighVoltage_Small 4025,1660 r0 top
High_Voltage "DANGER HIGH VOLTAGE" IEC_HighVoltage_Small 1585,1745 r0 top
J1 "OSTVN02A150" On-Shore_OSTVN02A150 5367.4,2365.59 r90 top
J2 "TSW-106-08-T-D-RA" AB12-DEST 5296.77,1064.96 r90 top
J3 "TSW-106-08-T-D-RA" AB12-DEST 250,2330 r270 top
J4 "90122-0763" Molex_90122-0763 5274.33,524.96 r180 top
Logo1 "Pb-Free Symbol" Pb-Free_Overlay_Small 4570,85 r0 top
Logo2 "FCC disclaimer" FCC_disclaimer 4655,60 r180 bottom
MD1 "FF400R07A01E3S6XKSA2" FP-FF400R07A01E3S6XKSA2_PG-MDIP-14-MFG 2656.14,1574.33 r180 bottom
Q1 "BC857C-7-F" SOT-23#1 2180.24,921.26 r90 top value="45 V"
Q2 "BC857C-7-F" SOT-23#1 3328.84,2250 r270 top value="45 V"
Q3 "SI2318CDS-T1-GE3" SOT-23#1 2035,1816.57 r270 bottom value=40V
Q4 "MMST3904-7-F" SOT-323 3848.98,1456.58 r270 top value="40 V"
Q5 "SI2318CDS-T1-GE3" SOT-23#2 2735,1273.43 r90 bottom value=40V
Q6 "DMN5L06WK-7" SOT-323 4407.91,2101.3 r0 top value=50V
Q7 "DPBT8105-7" SOT-23#1 4380,1810 r180 top value="60 V"
Q8 "DPBT8105-7" SOT-23#1 3980,1910 r0 top value="60 V"
Q9 "SI2318CDS-T1-GE3" SOT-23#1 3710,2145 r270 top value=40V
Q10 "DNBT8105-7" SOT-23#1 4275,2030 r270 top value="60 V"
Q11 "DNBT8105-7" SOT-23#1 4142.91,2011.3 r270 top value="60 V"
Q12 "DMN5L06WK-7" SOT-323 1125.67,1000 r180 top value=50V
Q13 "MMBT2907AT-7-F" SOT-523 1075,1250 r0 top value="60 V"
Q14 "MMBT2907AT-7-F" SOT-523 1290,1265 r90 top value="60 V"
Q15 "MMBT3904T-7-F" SOT-523 1260,1050 r90 top value="40 V"
Q16 "MMBT3904T-7-F" SOT-523 1445,1080 r90 top value="40 V"
Q17 "SI2318CDS-T1-GE3" SOT-23#1 1810,960 r90 top value=40V
R1 "CRCW0805100RFKEA" 0805_HV 865,2345 r90 top value=100
R2 "ERJ-3GEY0R00V" 0603 1515,2495.5 r0 top value=0
R3 "CRCW080520K0FKEA" 0805_HV 1578.14,2352.61 r90 top value=20.0k
R4 "CRCW04023K32FKED" 0402 5157.4,1954.13 r270 top value=3.32k
R5 "CRCW0805100KFKEA" 0805_HV 700,2040 r0 top value=100k
R6 "CRCW0603154KFKEA" 0603 717.95,2190.87 r270 top value=154k
R7 "CRCW0603301KFKEA" 0603 457.1,2240 r270 top value=301k
R8 "ERJ-3GEY0R00V" 0603 1595,2055 r0 top value=0
R9 "CRCW0603976KFKEA" 0603 567.1,2022.61 r0 top value=976k
R10 "CRCW080510R0JNEA" 0805_HV 3600,1020 r0 bottom value=10
R11 "CRCW080512K1FKEA" 0805_HV 495,2110 r180 top value=12.1k
R12 "CRCW0805100RFKEA" 0805_HV 4776.1,996.85 r270 top value=100
R13 "ERJ-3GEY0R00V" 0603 4108.98,840 r180 top value=0
R14 "CRCW080520K0FKEA" 0805_HV 4055,949.76 r270 top value=20.0k
R15 "CRCW080510R0JNEA" 0805_HV 1880,2150 r270 bottom value=10
R16 "CRCW0805100KFKEA" 0805_HV 4906.1,1316.85 r180 top value=100k
R17 "CRCW0603154KFKEA" 0603 4910.13,1156.84 r90 top value=154k
R18 "CRCW0603301KFKEA" 0603 5165,1097.68 r90 top value=301k
R19 "ERJ-3GEY0R00V" 0603 4020.43,1180 r180 top value=0
R20 "CRCW0603976KFKEA" 0603 5056.1,1316.85 r180 top value=976k
R21 "CRCW080512K1FKEA" 0805_HV 5115,1235 r0 top value=12.1k
R22 "CRCW1206221KFKEA" 1206 600,1270 r90 top value=221k
R23 "CRCW1206221KFKEA" 1206 438.74,1330 r180 top value=221k
R24 "CRCW1206221KFKEA" 1206 228.74,1330 r180 top value=221k
R25 "CRCW1206221KFKEA" 1206 176.38,1510 r90 top value=221k
R26 "CRCW1206221KFKEA" 1206 348.74,1570 r0 top value=221k
R27 "CRCW1206221KFKEA" 1206 558.74,1570 r0 top value=221k
R28 "CRCW08052K49FKEA" 0805_HV 700,1110 r90 top value=2.49k
R29 "CRCW06030000Z0EA" 0603 475,144.13 r270 bottom value=0
R30 "CRCW060315K0FKEA" 0603 350,95 r90 bottom value=15.0k
R31 "CRCW08052K49FKEA" 0805_HV 566.38,1020 r0 top value=2.49k
R32 "CRCW06034K64FKEA" 0603 450.51,181.3 r180 top value=4.64k
R33 "CRCW06034K64FKEA" 0603 360,148.98 r90 top value=4.64k
R34 "CRCW06031K21FKEA" 0603 527.68,910 r90 top value=1.21k
R35 "CRCW06031K21FKEA" 0603 607.68,910 r90 top value=1.21k
R36 "CRCW060349R9FKEA" 0603 560,240 r90 bottom value=49.9
R37 "CRCW06034K64FKEA" 0603 530,40 r180 top value=4.64k
R38 "CRCW06034K64FKEA" 0603 300,148.98 r90 top value=4.64k
R39 "CRCW040210R0FKED" 0402 588.35,200 r90 top value=10.0
R40 "CRCW060315K0FKEA" 0603 160,320 r180 top value=15.0k
R41 "CRCW04020000Z0ED" 0402 3235,745 r0 top value=0
R42 "CRCW040210R0FKED" 0402 538.35,200 r90 top value=10.0
R43 "CRCW06032K49FKEA" 0603 3788.5,1080 r270 top value=2.49k
R44 "CRCW06032K49FKEA" 0603 3868.5,1080 r270 top value=2.49k
R45 "CRCW040249K9FKED" 0402 2345,910 r0 top value=49.9k
R46 "CRCW040249K9FKED" 0402 3245,2170 r180 top value=49.9k
R47 "CRCW0402240KFKED" 0402 2325,1160 r0 top value=240k
R48 "CRCW040210K0FKED" 0402 2345,860 r180 top value=10.0k
R49 "CRCW0402240KFKED" 0402 3375,2035 r180 top value=240k
R50 "CRCW040210K0FKED" 0402 3225,2260 r90 top value=10.0k
R51 "CRCW04021K82FKED" 0402 2240,1120 r90 top value=1.82k
R52 "CRCW060311K0FKEA" 0603 2140,1040 r180 top value=11.0k
R53 "CRCW060311K0FKEA" 0603 3436.54,2223.59 r0 top value=11.0k
R54 "CRCW04021K82FKED" 0402 3375,1990 r0 top value=1.82k
R55 "CRCW06033K32FKEA" 0603 2024.19,974.45 r90 top value=3.32k
R56 "CRCW04025K76FKED" 0402 2240,1010 r90 top value=5.76k
R57 "CRCW04025K76FKED" 0402 3160,2260 r270 top value=5.76k
R58 "CRCW080510R0JNEA" 0805_HV 1865,2985 r0 top value=10
R59 "RMCF0402FT10K0" 0402 2485,2945 r90 top value=10.0k
R60 "RMCF0402FT10K0" 0402 2435,2945 r90 top value=10.0k
R61 "RMCF0402FT10K0" 0402 2387.18,2945.35 r90 top value=10.0k
R62 "Resistor" 0402 2689.47,2935 r0 top value=100
R63 "CRCW20105R10JNEF" 2010 2595,2070 r270 top value=5.1
R64 "Resistor" 0402 2589.47,2935 r180 top value=100
R65 "CRCW20105R10JNEF" 2010 2745,2070 r270 top value=5.1
R66 "CRCW20105R10JNEF" 2010 2895,2070 r270 top value=5.1
R67 "CRCW20105R10JNEF" 2010 2290,2070 r270 top value=5.1
R68 "CRCW20105R10JNEF" 2010 2440,2070 r270 top value=5.1
R69 "CRCW060310K0FKEA" 0603 2328.31,1730 r180 top value=10.0k
R70 "CRCW20105R10JNEF" 2010 2140,2070 r270 top value=5.1
R71 "CRCW06030000Z0EA" 0603 2195,2940 r270 top value=0
R72 "CRCW060349R9FKEA" 0603 2090,2395 r90 top value=49.9
R73 "TNPW060310R0BEEA" 0603 2105,2260 r180 bottom value=10.0
R74 "CRCW12062R00FKEA" 1206 2700,1805 r270 bottom value=2.00
R75 "CRCW06033K48FKEA" 0603 717.95,2920.83 r90 top value=3.48k
R76 "CRCW06033K48FKEA" 0603 802.95,2920.83 r90 top value=3.48k
R77 "CRCW06033K48FKEA" 0603 887.95,2920.83 r90 top value=3.48k
R78 "CRCW04020000Z0ED" 0402 2716.26,1770 r270 top value=0
R79 "CRCW06030000Z0EA" 0603 2170,1735 r0 bottom value=0
R80 "CRCW12062R00FKEA" 1206 2735,2275 r180 top value=2.00
R81 "CRCW060310K2FKEA" 0603 2015,1945 r0 bottom value=10.2k
R82 "CRCW04020000Z0ED" 0402 3330,1350 r90 top value=0
R83 "CRCW080510R0JNEA" 0805_HV 3510,260 r270 top value=10
R84 "CRCW12062R00FKEA" 1206 3420,1390 r90 bottom value=2.00
R85 "RMCF0402FT10K0" 0402 2924.75,120 r270 top value=10.0k
R86 "RMCF0402FT10K0" 0402 3027.38,120 r270 top value=10.0k
R87 "RMCF0402FT10K0" 0402 3158.69,120 r270 top value=10.0k
R88 "Resistor" 0402 2640,120 r270 top value=100
R89 "CRCW20105R10JNEF" 2010 2875,1065 r90 top value=5.1
R90 "Resistor" 0402 2782.13,120 r270 top value=100
R91 "CRCW20105R10JNEF" 2010 2570,1065 r90 top value=5.1
R92 "CRCW080510K0FKEA" 0805_HV 3858.98,1336.58 r0 top value=10.0k
R93 "CRCW20105R10JNEF" 2010 2725,1065 r90 top value=5.1
R94 "CRCW20105R10JNEF" 2010 3335,1065 r90 top value=5.1
R95 "CRCW20105R10JNEF" 2010 3185,1065 r90 top value=5.1
R96 "CRCW060310K0FKEA" 0603 2990,1340 r180 top value=10.0k
R97 "RT0805BRD072K49L" 0805_HV 3678.98,1336.58 r0 top value=2.49k
R98 "CRCW20105R10JNEF" 2010 3030,1065 r90 top value=5.1
R99 "CRCW06030000Z0EA" 0603 3410,190 r90 top value=0
R100 "TNPW060310R0BEEA" 0603 3230,880 r0 top value=10.0
R101 "CRCW060349R9FKEA" 0603 3435,680 r180 top value=49.9
R102 "CRCW06033K48FKEA" 0603 5060,235 r270 top value=3.48k
R103 "CRCW06033K48FKEA" 0603 5130,245 r270 top value=3.48k
R104 "CRCW06033K48FKEA" 0603 5205,245 r270 top value=3.48k
R105 "CRCW06030000Z0EA" 0603 2845,1355 r0 bottom value=0
R106 "CRCW12062R00FKEA" 1206 2720,850 r0 top value=2.00
R107 "CRCW060310K2FKEA" 0603 2735,1145 r0 bottom value=10.2k
R108 "ERJ-3GEY0R00V" 0603 5310,1515 r90 top value=0
R109 "ERJ-3GEY0R00V" 0603 5375,1470 r270 top value=0
R110 "CRCW06031K02FKEA" 0603 3035,2985 r180 top value=1.02k
R111 "CRCW060310K2FKEA" 0603 4000,3015 r270 top value=10.2k
R112 "CRCW06031K02FKEA" 0603 2381.3,143.5 r0 top value=1.02k
R113 "CRCW060310K2FKEA" 0603 1520,140 r90 top value=10.2k
R114 "CRCW060310K2FKEA" 0603 3415,2915 r270 top value=10.2k
R115 "CRCW0603100KFKEA" 0603 3185,2885 r270 top value=100k
R116 "CRCW060310K2FKEA" 0603 2035,90 r90 top value=10.2k
R117 "CRCW0603100KFKEA" 0603 2281.3,243.5 r270 top value=100k
R118 "CRCW08052K49FKEA" 0805_HV 3855,2870 r270 top value=2.49k
R119 "CRCW08052K49FKEA" 0805_HV 4580,2110 r90 top value=2.49k
R120 "CRCW08052K49FKEA" 0805_HV 4725,3005 r180 top value=2.49k
R121 "CRCW060310K0FKEA" 0603 3710,2385 r180 top value=10.0k
R122 "CRCW080510K0FKEA" 0805_HV 3587.91,2161.3 r270 top value=10.0k
R123 "CRCW08054K02FKEA" 0805_HV 3947.91,2341.3 r0 top value=4.02k
R124 "CRCW0603470RJNEA" 0603 4382.24,2241.3 r270 top value=470
R125 "CRCW06034K99FKEA" 0603 4435,1916.3 r0 top value=4.99k
R126 "CRCW08052K49FKEA" 0805_HV 3645,2870 r270 top value=2.49k
R127 "CRCW06034K99FKEA" 0603 3842.52,1915 r270 top value=4.99k
R128 "CRCW08053K01FKEA" 0805_HV 3830,2145 r90 top value=3.01k
R129 "CRCW06031K02FKEA" 0603 4305,1916.3 r0 top value=1.02k
R130 "CRCW06032K49FKEA" 0603 4132.91,1871.3 r270 top value=2.49k
R131 "CRCW060315K0FKEA" 0603 3825,2360 r270 top value=15.0k
R132 "CRCW08053K01FKEA" 0805_HV 3587.91,2321.3 r270 top value=3.01k
R133 "CRCW0603100RFKEA" 0603 4272.04,3011.3 r270 top value=100
R134 "CRCW060310K2FKEA" 0603 4310,2280 r270 top value=10.2k
R135 "CRCW060310K2FKEA" 0603 4200,1870 r270 top value=10.2k
R136 "CRCW0603100RFKEA" 0603 4067.91,3021.3 r270 top value=100
R137 "CRCW060310K2FKEA" 0603 3587.52,1896.3 r0 top value=10.2k
R138 "CRCW060310K2FKEA" 0603 4275,2135 r0 top value=10.2k
R139 "CRCW060310K2FKEA" 0603 4177.91,2241.3 r270 top value=10.2k
R140 "CRCW080524R9FKEA" 0805_HV 3507.52,1976.3 r0 top value=24.9
R141 "CRCW06034K99FKEA" 0603 3707.91,2290.04 r0 top value=4.99k
R142 "CRCW060310K2FKEA" 0603 4130,2135 r0 top value=10.2k
R143 "CRCW08052K49FKEA" 0805_HV 1710,280 r180 top value=2.49k
R144 "CRCW08052K49FKEA" 0805_HV 985.67,1000 r180 top value=2.49k
R145 "CRCW08052K49FKEA" 0805_HV 920,295 r0 top value=2.49k
R146 "CRCW0603470RJNEA" 0603 1155.67,860 r90 top value=470
R147 "CRCW060310K0FKEA" 0603 1795,790 r0 top value=10.0k
R148 "CRCW080510K0FKEA" 0805_HV 1930,1015 r90 top value=10.0k
R149 "CRCW06034K99FKEA" 0603 1105.67,1140 r180 top value=4.99k
R150 "CRCW08054K02FKEA" 0805_HV 1555,825 r180 top value=4.02k
R151 "CRCW08052K49FKEA" 0805_HV 1890,280 r180 top value=2.49k
R152 "CRCW06034K99FKEA" 0603 1510,1208.54 r90 top value=4.99k
R153 "CRCW06031K02FKEA" 0603 1235.67,1140 r180 top value=1.02k
R154 "CRCW06032K49FKEA" 0603 1365,1140 r90 top value=2.49k
R155 "CRCW08053K01FKEA" 0805_HV 1690,975 r270 top value=3.01k
R156 "CRCW0603100RFKEA" 0603 1270.87,140 r90 top value=100
R157 "CRCW060310K2FKEA" 0603 1230,830 r90 top value=10.2k
R158 "CRCW060310K2FKEA" 0603 1255,1360 r180 top value=10.2k
R159 "CRCW0603100RFKEA" 0603 1450,140 r90 top value=100
R160 "CRCW060310K2FKEA" 0603 1500,1408.54 r180 top value=10.2k
R161 "CRCW060315K0FKEA" 0603 1695,820 r90 top value=15.0k
R162 "CRCW08053K01FKEA" 0805_HV 1930,841.26 r90 top value=3.01k
R163 "CRCW060310K2FKEA" 0603 1265.67,960 r180 top value=10.2k
R164 "CRCW060310K2FKEA" 0603 1370,860 r90 top value=10.2k
R165 "CRCW080524R9FKEA" 0805_HV 1580,1328.54 r180 top value=24.9
R166 "CRCW060310K2FKEA" 0603 1405,970 r180 top value=10.2k
R167 "CRCW06034K99FKEA" 0603 1810,855 r180 top value=4.99k
R168 "CRCW0603100RFKEA" 0603 4336.75,2951.3 r270 top value=100
R169 "CRCW0603100RFKEA" 0603 1211.17,140 r90 top value=100
R170 "CRCW06033K32FKEA" 0603 3445,2157.76 r0 top value=3.32k
R171 "CRCW06039K09FKEA" 0603 3541.57,1456.58 r0 top value=9.09k
S1 "SKRKAEE010" SW_SKRKAEE010 3747.91,2971.3 r270 top
S2 "SKRKAEE010" SW_SKRKAEE010 4710,2890 r0 top
S3 "SKRKAEE010" SW_SKRKAEE010 3537.91,2971.3 r270 top
S4 "SKRKAEE010" SW_SKRKAEE010 1710,130 r90 top
S5 "SKRKAEE010" SW_SKRKAEE010 895,135 r90 top
S6 "SKRKAEE010" SW_SKRKAEE010 1880,130 r90 top
T1 "ZA9710-AE" FP-ZA9710-AE_SMT_8-MFG 1180,2272.8 r0 top
T? "ZA9710-AE" FP-ZA9710-AE_SMT_8-MFG 4460,1086.8 r180 top
TP1 "5005" Keystone5005 915,1947.4 r0 top
TP2 "5006" Keystone5006 4970,3000 r0 top
TP3 "5005" Keystone5005 4690,1430 r0 top
TP4 "0508-0-00-15-00-00-03-0" Mill-Max_0508-0-00-15-00-00-03-0 635,60 r0 top
TP5 "0508-0-00-15-00-00-03-0" Mill-Max_0508-0-00-15-00-00-03-0 455,105 r0 top
TP6 "0508-0-00-15-00-00-03-0" Mill-Max_0508-0-00-15-00-00-03-0 1720,1205 r0 top
TP7 "0508-0-00-15-00-00-03-0" Mill-Max_0508-0-00-15-00-00-03-0 3125,2440 r0 top
TP8 "0508-0-00-15-00-00-03-0" Mill-Max_0508-0-00-15-00-00-03-0 2515,740 r0 top
TP9 "0508-0-00-15-00-00-03-0" Mill-Max_0508-0-00-15-00-00-03-0 2875,2420 r0 top
TP10 "0508-0-00-15-00-00-03-0" Mill-Max_0508-0-00-15-00-00-03-0 2980,2285 r0 top
TP11 "0508-0-00-15-00-00-03-0" Mill-Max_0508-0-00-15-00-00-03-0 2035,1875 r90 top
TP12 "0508-0-00-15-00-00-03-0" Mill-Max_0508-0-00-15-00-00-03-0 1955,1925 r0 top
TP13 "5122" Keystone5122 5250,2770 r0 top
TP14 "5122" Keystone5122 4710,570 r0 top
TP15 "5122" Keystone5122 5440,2835 r0 top
TP16 "5122" Keystone5122 4933.78,635 r0 top
TP17 "0508-0-00-15-00-00-03-0" Mill-Max_0508-0-00-15-00-00-03-0 3010,2465 r90 top
TP18 "5005" Keystone5005 4990,2595 r0 top
TP19 "0508-0-00-15-00-00-03-0" Mill-Max_0508-0-00-15-00-00-03-0 2460,845 r0 top
TP20 "0508-0-00-15-00-00-03-0" Mill-Max_0508-0-00-15-00-00-03-0 2705,1260 r90 top
TP21 "0508-0-00-15-00-00-03-0" Mill-Max_0508-0-00-15-00-00-03-0 3486.5,1295 r0 top
TP22 "0508-0-00-15-00-00-03-0" Mill-Max_0508-0-00-15-00-00-03-0 2670,705 r90 top
TP23 "5006" Keystone5006 105,1920 r0 top
TP24 "5006" Keystone5006 5430,1775 r0 top
TP25 "0508-0-00-15-00-00-03-0" Mill-Max_0508-0-00-15-00-00-03-0 3190,2996.72 r0 top
TP26 "5005" Keystone5005 2525,135 r0 top
U1 "TPS7B8250QDGNRQ1" DGN0008D_N 5317.4,1954.13 r180 top
U2 "LM5180QNGURQ1" NGU0008C 587.1,2245.76 r180 top
U3 "TPS70950QDBVRQ1" DBV0005A_N 3578.98,1071.26 r90 top
U4 "TLV71333PQDBVRQ1" DBV0005A_N 3578.98,871.26 r270 top
U5 "TPS70950QDBVRQ1" DBV0005A_N 1780.28,2142.14 r270 top
U6 "LM5180QNGURQ1" NGU0008C 5040.13,1096.84 r0 top
U7 "TLV71333PQDBVRQ1" DBV0005A_N 1780.7,2325.88 r90 top
U8 "AMC1311DWVR" DWV0008A 566.38,511.26 r270 top
U9 "OPA320AQDBVRQ1" DBV0005A_N 338.74,290 r0 top
U10 "ISO7742FQDWRQ1" DW0016B_HV 3862.05,499.37 r90 top
U11 "ADS7049QDCURQ1" DCU0008A_N 3818.98,863.62 r90 top
U12 "TPS3700QDDCRQ1" DDC0006A_N 2340,1055 r270 top
U13 "TPS3700QDDCRQ1" DDC0006A_N 3210,2030 r0 top
U14 "UCC21732QDWQ1" DW0016B_HV 2487.18,2625.35 r90 top
U15 "UCC21732QDWQ1" DW0016B_HV 2983.31,499.37 r270 top
U16 "TL431AQDBZRQ1" DBZ0003A_N 3678.98,1456.58 r180 top
U17 "SN74AHC1G08QDBVRQ1" DBV0005A_N 5190,1515 r0 top
U18 "TLV271QDBVRQ1" DBV0005A_N 3301.1,2915 r0 top
U19 "TLV271QDBVRQ1" DBV0005A_N 2132.4,160.9 r90 top
U20 "TLV3201AIDCKR" DCK0005A_N 3937.91,2251.3 r0 top
U21 "ISO7762FQDWQ1" DW0016B_HV 4177.91,2621.3 r270 top
U22 "ISO7762FQDWQ1" DW0016B_HV 1361.26,499.37 r90 top
U23 "TLV3201AIDCKR" DCK0005A_N 1570,915 r180 top
ZZ1 "This Assembly Note is for PCB labels only" AssemblyNoteLabel 185,3938 r0 top
ZZ2 "These assemblies are ESD sensitive, ESD precautions shall be observed." AssemblyNote 185,3829.11 r0 top
ZZ3 "These assemblies must be clean and free from flux and all contaminants. Use of no clean flux is not acceptable." AssemblyNote 185,3740.56 r0 top
ZZ4 "These assemblies must comply with workmanship standards IPC-A-610 Class 2, unless otherwise specified." AssemblyNote 185,3652 r0 top

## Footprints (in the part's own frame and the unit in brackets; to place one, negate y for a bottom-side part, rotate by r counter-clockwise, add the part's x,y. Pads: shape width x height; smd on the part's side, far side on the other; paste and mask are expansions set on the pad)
0402 [mm] "0402 from SM-752 data"
  rect 0.8x0.6 smd: 1(-0.6,0) 2(0.6,0)
  silkscreen extent -1.22,-0.52 1.22,0.52, body extent -0.55,-0.3 0.55,0.3, height 0.6
0603 [mm] "0603 from SM-752 data"
  rect 1x0.95 smd: 1(-0.8,0) 2(0.8,0)
  silkscreen extent -1.52,-0.69 1.52,0.69, body extent -0.87,-0.47 0.87,0.47, height 1
0805_HV [mil] "0805 with 30mil clearance between pads"
  rect 50x63 smd: 1(-40,0) 2(40,0)
  silkscreen extent -74,-40 74,40, body extent -43,-29 43,29, height 57
1206 [mm] "1206 from SM-752 data"
  rect 1.3x1.85 smd: 1(-1.45,0) 2(1.45,0)
  silkscreen extent -2.4,-1.21 2.4,1.21, body extent -1.7,-0.9 1.7,0.9, height 1.35
1206_180 [mm] "1206_180"
  rect 1.1x1.6 smd: 1(-1.7,0) 2(1.7,0)
  silkscreen extent -0.9,-1 0.9,1, body extent -1.75,-0.95 1.75,0.95, height 1.8
1210_220 [mm] "1210"
  rect 1.3x2.7 smd: 1(-1.45,0) 2(1.45,0)
  silkscreen extent -2.32,-1.57 2.32,1.57, body extent -1.7,-1.35 1.7,1.35, height 2.2
2010 [mm] "Chip Capacitor, Body 5.08x2.54mm, IPC Medium Density"
  rect 1.6x2.7 smd: 1(-2.3,0) 2(2.3,0)
  silkscreen extent -3.42,-1.65 3.42,1.65, body extent -2.73,-1.45 2.73,1.45, height 1.66
2220_250 [mm] "2220"
  rect 1.6x5.3 smd: 1(-2.6,0) 2(2.6,0)
  silkscreen extent -3.69,-2.94 3.69,2.94, body extent -2.95,-2.62 2.95,2.62, height 2.5
AB12-DEST [mil] "Samtec right angle header, pins flipped from convention"
  rect 70x70 hole 40: 1(-250,50)
  round 70 hole 40: 2(-250,-50) 3(-150,50) 4(-150,-50) 5(-50,50) 6(-50,-50) 7(50,50) 8(50,-50) 9(150,50) 10(150,-50) 11(250,50) 12(250,-50)
  silkscreen extent -300,-479 300,100, body extent -300,-440 300,63, height 219
AssemblyNote [mil] "Assembly Note"
AssemblyNoteLabel [mil] "Assembly Note for PCB Labels"
DBV0005A_N [mm] "SOT23, 5-Leads, Body 2.9x1.6mm, Pitch 0.95mm, Lead Span 2.8mm, IPC Medium Density"
  rrect17% 1x0.6 smd: 1(-1.375,0.95) 2(-1.375,0) 3(-1.375,-0.95) 4(1.375,-0.95) 5(1.375,0.95)
  silkscreen extent -1.63,-1.55 0.38,1.55, body extent -1.42,-1.46 1.42,1.46, height 1.09
DBZ0003A_N [mm] "SOT23, 3-Leads, Body 2.9x1.3mm, Pitch 0.95mm, Lead Span 2.4mm, IPC Medium Density"
  rrect17% 1x0.6 smd: 1(-1.2,0.95) 2(-1.2,-0.95) 3(1.2,0)
  silkscreen extent 0.2,-1.5 0.7,1.5, body extent -1.26,-1.46 1.26,1.46, height 0.98
DCK0005A_N [mm] "SOT353, 5-Leads, Body 2x1.3mm, Pitch 0.65mm, Lead Span 2.1mm, IPC Medium Density"
  rrect25% 0.85x0.4 smd: 1(-1.125,0.65) 2(-1.125,0) 3(-1.125,-0.65) 4(1.125,-0.65) 5(1.125,0.65)
  silkscreen extent -1.48,-1.02 0.55,1.1, body extent -1.14,-1 1.14,1, height 0.95
DCU0008A_N [mm] "TSSOP, 8-Leads, Body 2x2.3mm, Pitch 0.5mm, IPC Medium Density"
  oval 0.8x0.3 smd: 1(-1.6,0.75) 2(-1.6,0.25) 3(-1.6,-0.25) 4(-1.6,-0.75) 5(1.6,-0.75) 6(1.6,-0.25) 7(1.6,0.25) 8(1.6,0.75)
  silkscreen extent -1.05,-1.05 0.38,1.05, body extent -1.56,-1 1.56,1, height 0.9
DDC0006A_N [mm]
  rrect17% 1x0.6 smd: 1(-1.375,0.95) 2(-1.375,0) 3(-1.375,-0.95) 4(1.375,-0.95) 5(1.375,0) 6(1.375,0.95)
  silkscreen extent -1.75,-1.52 0.7,1.53, body extent -1.43,-1.48 1.43,1.49, height 0.92
DGN0008D_N [mm] "TSOP, 8-Leads, Body 3x3mm, Pitch 0.65mm, Thermal Pad 1.89x1.57mm, IPC Medium Density"
  rrect100% 1.35x0.45 smd: 1(-2.225,0.975) 2(-2.225,0.325) 3(-2.225,-0.325) 4(-2.225,-0.975) 5(2.225,-0.975) 6(2.225,-0.325) 7(2.225,0.325) 8(2.225,0.975)
  rrect6% 1.57x1.89 smd: 9(0,0)
  silkscreen extent -2.73,-1.55 0.95,1.55, body extent -2.46,-1.5 2.46,1.5, height 1.1
DW0016B_HV [mm] "SOIC-16, HV/isolation option"
  rrect17% 1.65x0.6 smd: 1(-4.875,4.445) 2(-4.875,3.175) 3(-4.875,1.905) 4(-4.875,0.635) 5(-4.875,-0.635) 6(-4.875,-1.905) 7(-4.875,-3.175) 8(-4.875,-4.445) 9(4.875,-4.445) 10(4.875,-3.175) 11(4.875,-1.905) 12(4.875,-0.635) 13(4.875,0.635) 14(4.875,1.905) 15(4.875,3.175) 16(4.875,4.445)
  body extent -5.17,-5.15 5.17,5.15, height 2.59
DWV0008A [mm] "SOIC, 8-Leads, Body 5.95x7.6mm (max), Pitch 1.27mm"
  rrect17% 1.8x0.6 smd: 1(-5.45,1.905) 2(-5.45,0.635) 3(-5.45,-0.635) 4(-5.45,-1.905) 5(5.45,-1.905) 6(5.45,-0.635) 7(5.45,0.635) 8(5.45,1.905)
  silkscreen extent -6.25,-2.95 2.98,2.95, body extent -5.77,-2.92 5.77,2.93, height 2.67
FCC_disclaimer [mil]
Fiducial10-20 [mm]
  round 1 smd mask+0.5: 1(0,0)
  Top Layer keep-out circle w1.178: c0,0 r0.5
FP-FF400R07A01E3S6XKSA2_PG-MDIP-14-MFG [mm]
  rrect4% 2.45x2.45 hole 1.6 paste-1000 mask+0: 4(-15.5,-2.65)
  round 2.45 hole 1.6 paste-1000 mask+0: 5(-13.2,0.85) 6(-10.9,-2.65) 7(-8.6,0.85) 8(-6.3,-2.65) 9(1.3,0.85) 10(3.6,-2.65) 11(5.9,0.85) 12(8.2,-2.65) 13(10.5,0.85) 14(15.5,-2.65)
  body extent -21,-3.2 21,1.5, height 61.9
FP-ZA9710-AE_SMT_8-MFG [mm]
  rrect8% 2.03x1.27 smd paste+0 mask+0: 1(-5.715,3.75) 2(-5.715,1.25) 3(-5.715,-1.25) 4(-5.715,-3.75) 5(5.715,-3.75) 6(5.715,-1.25) 7(5.715,1.25) 8(5.715,3.75)
  silkscreen extent -7.43,-5.65 6.61,5.65, body extent -6.83,-5.75 6.83,5.75, height 0.25
IEC_HighVoltage_Small [mil]
  silkscreen extent -107,-88 107,97
Keystone5005 [mil] "Keystone Compact loops"
  round 87 hole 63: 1(0,0)
  silkscreen extent -70,-70 70,70, body extent -63,-63 62,63, height 225
Keystone5006 [mil] "Keystone Compact loops"
  round 87 hole 63: 1(0,0)
  silkscreen extent -70,-70 70,70, body extent -63,-63 62,63, height 225
Keystone5122 [mil] "Keystone Compact loops"
  round 87 hole 63: 1(0,0)
  silkscreen extent -70,-70 70,70, body extent -63,-63 62,63, height 225
KY_700x500x1000 [mm] "TH, 2- Leads, Body 7x5mm, Pin Spacing 7.5mm"
  round 1.4 hole 0.9: 1(-3.75,0) 2(3.75,0)
  silkscreen extent -3.5,-2.5 3.5,2.5, body extent -4.05,-2.5 4.05,2.5, height 9.97
Mill-Max_0508-0-00-15-00-00-03-0 [mm] "PCB Pin, 20mil Dia, TH"
  round 1.75 smd: 1(0,0)
  silkscreen extent -1.1,-1.1 1.1,1.1, body extent -0.72,-0.74 0.74,0.74, height 4.44
Molex_90122-0763 [mm] "Header, 2.54mm, 3x2, R/A, TH"
  rrect50% 1.5x1.5 hole 1: 1(-1.27,2.54)
  round 1.5 hole 1: 2(1.27,2.54) 3(-1.27,0) 4(1.27,0) 5(-1.27,-2.54) 6(1.27,-2.54)
  silkscreen extent -5.6,-3.9 -2.6,3.9, body extent -12.27,-3.81 1.57,3.81, height 6.35
NGU0008C [mm] "SON, 8-Leads, Body 4x4mm, Pitch 0.8mm"
  rrect33% 0.6x0.3 smd: 1(-1.9,1.2) 2(-1.9,0.4) 3(-1.9,-0.4) 4(-1.9,-1.2) 5(1.9,-1.2) 6(1.9,-0.4) 7(1.9,0.4) 8(1.9,1.2)
  rrect8% 1.75x1.31 on Top Paste: 9(0,0.755) 9(0,-0.755)
  rrect5% 1.98x3 smd paste-1.5: 9(0,0)
  silkscreen extent -2.15,-2.15 2.15,2.15, body extent -2,-2 2,2, height 0.77
On-Shore_OSTVN02A150 [mm] "Terminal Block, 2.54mm, 2-pole, Brass, TH"
  rect 1.8x1.8 hole 1.3: 1(-1.27,0)
  round 1.8 hole 1.3: 2(1.27,0)
  silkscreen extent -3.1,-3.25 2.77,3.25, body extent -2.77,-3.25 2.77,3.25, height 8.51
Pb-Free_Overlay_Small [mil]
  silkscreen extent -46,-46 46,46
PowerDI123 [mm] "Diodes Inc recommended land pattern, document number DS30628 Rev. 6-2"
  rect 2.2x1.4 smd: 1(-1.275,0)
  rect 0.9x1.4 smd: 2(1.275,0)
  silkscreen extent -3.1,-1.09 1.76,1.09, body extent -2.38,-0.97 1.52,0.96, height 1
SMA [mm] "Molded Diode, 2-Leads, Body 4.3x2.6mm, IPC Medium Density, based on OnSemi component dimensions and land pattern"
  rect 2x2 smd: 1(-2,0) 2(2,0)
  silkscreen extent -3.66,-1.57 2.79,1.57, body extent -2.6,-1.3 2.6,1.3, height 2.42
SMB [mil] "Molded Diode, 2-Leads, Body 5.4x3.6mm, IPC Medium Density, based on OnSemi component dimensions"
  rect 85x107.99 smd: 1(-87.01,0) 2(87.01,0)
  silkscreen extent -155,-82 125,82, body extent -106,-71 106,71, height 91
SOD882 [mm] "NXP Semiconductor"
  rect 0.4x0.7 smd paste-0.05: 1(-0.35,0) 2(0.35,0)
  silkscreen extent -0.95,-0.35 -0.72,0.35, body extent -0.51,-0.31 0.51,0.31, height 0.51
SOD-123 [mm] "On Semi recommended land pattern"
  rect 0.915x1.22 smd: 1(-1.637,0) 2(1.637,0)
  silkscreen extent -2.74,-1.17 2.03,1.17, body extent -1.93,-0.9 1.93,0.9, height 1.35
SOD-123W [mm] "NXP recommended land pattern"
  rect 1.2x1.2 smd paste-0.05: 1(-1.4,0) 2(1.4,0)
  silkscreen extent -2.64,-1.14 1.68,1.14, body extent -1.85,-0.95 1.85,0.95, height 1.1
SOD-323 [mm] "NXP recommended land pattern"
  rect 0.6x0.6 smd paste-0.05: 1(-1.1,0) 2(1.1,0)
  silkscreen extent -2.06,-0.86 1.53,0.86, body extent -1.3,-0.67 1.3,0.68, height 1.1
SOD-523 [mm] "NXP Semiconductor recommended land pattern, nominal STEP model"
  rect 0.8x0.6 smd paste-0.05: 1(-0.55,0) 2(0.55,0)
  silkscreen extent -1.65,-0.66 1.2,0.66, body extent -0.8,-0.4 0.8,0.4, height 0.72
SOT-23#1 [mm] "SOT23, 3-Leads, Body 2.9x1.3mm, Pitch 0.95mm, Lead Span 2.5mm, IPC Medium Density"
  rrect50% 1x0.6 smd: 1(-1.2,0.95) 2(-1.2,-0.95) 3(1.2,0)
  silkscreen extent -1.62,-1.5 0.7,1.5, body extent -1.16,-1.45 1.21,1.45, height 1
SOT-23#2 [mm] "SOT23, 3-Leads, Body 2.9x1.3mm, Pitch 0.95mm, Lead Span 2.5mm, IPC Medium Density"
  rrect50% 1x0.6 smd: 1(-1.2,-0.95) 2(-1.2,0.95) 3(1.2,0)
  silkscreen extent -1.62,-1.5 0.7,1.5, body extent -1.16,-1.45 1.21,1.45, height 1
SOT-323 [mm] "Diodes Inc recommended land pattern.  2016-02-24"
  rrect21% 0.6x0.47 smd: 1(-0.95,0.65) 2(-0.95,-0.65) 3(0.95,0)
  silkscreen extent -1.14,-1.22 0.77,1.22, body extent -1.13,-1.13 1.12,1.12, height 1.13
SOT-523 [mm] "From Diodes Inc datasheet component parameters"
  rect 0.9x0.4 smd: 1(-0.8,0.5) 2(-0.8,-0.5) 3(0.8,0)
  silkscreen extent 0.02,-0.85 0.42,0.85, body extent -0.8,-0.8 0.8,0.8, height 0.79
SW_SKRKAEE010 [mm] "Alps recommended land pattern"
  rect 0.8x2 smd: 1(-2.1,0) 2(2.1,0)
  silkscreen extent -1.9,-1.44 1.92,1.44, body extent -2.4,-1.45 2.4,1.45, height 1.96
WL-SMCW_GREEN [mm] "WURTH"
  rect 0.8x0.8 smd: 1(-0.8,0) 2(0.8,0)
  silkscreen extent -1.9,-0.8 1.2,0.8, body extent -0.85,-0.45 0.85,0.45, height 0.8
WL-SMCW_RED [mm] "WURTH"
  rect 0.8x0.8 smd: 1(-0.8,0) 2(0.8,0)
  silkscreen extent -1.9,-0.8 1.2,0.8, body extent -0.85,-0.45 0.85,0.45, height 0.8

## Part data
C1 C23: "CAP, CERM, 10 μF, 100 V,+/- 10%, X7S, 2220", Cap_Case=2220, Manufacturer=TDK, Supplier Part Number 1=445-13408-1-ND, TempCo=X7S, Tolerance_%=10, Value1="0.003179 ohm", Value2=100V, ValueDisplayed=10μF
C2 C24: library part CMP-0082268-1, "CAP, CERM, 4.7 μF, 100 V,+/- 10%, X7S, AEC-Q200 Grade 1, 1210", Cap_Case=1210, Manufacturer=MuRata, Supplier Part Number 1=490-14484-1-ND, TempCo=X7S, Tolerance_%=10%, Value1="0.001 ohm", Value2=100V, ValueDisplayed=4.7μF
